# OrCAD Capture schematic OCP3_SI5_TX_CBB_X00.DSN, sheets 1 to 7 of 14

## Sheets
1 PAGE01 - TITLE AND BLOCK DIAG: title: OCP3 SI TX CBB GEN 5; rev: X00; company: Dell, Inc.; note: X07NT; note: 200 Dell Way; note: Round Rock, TX 78682
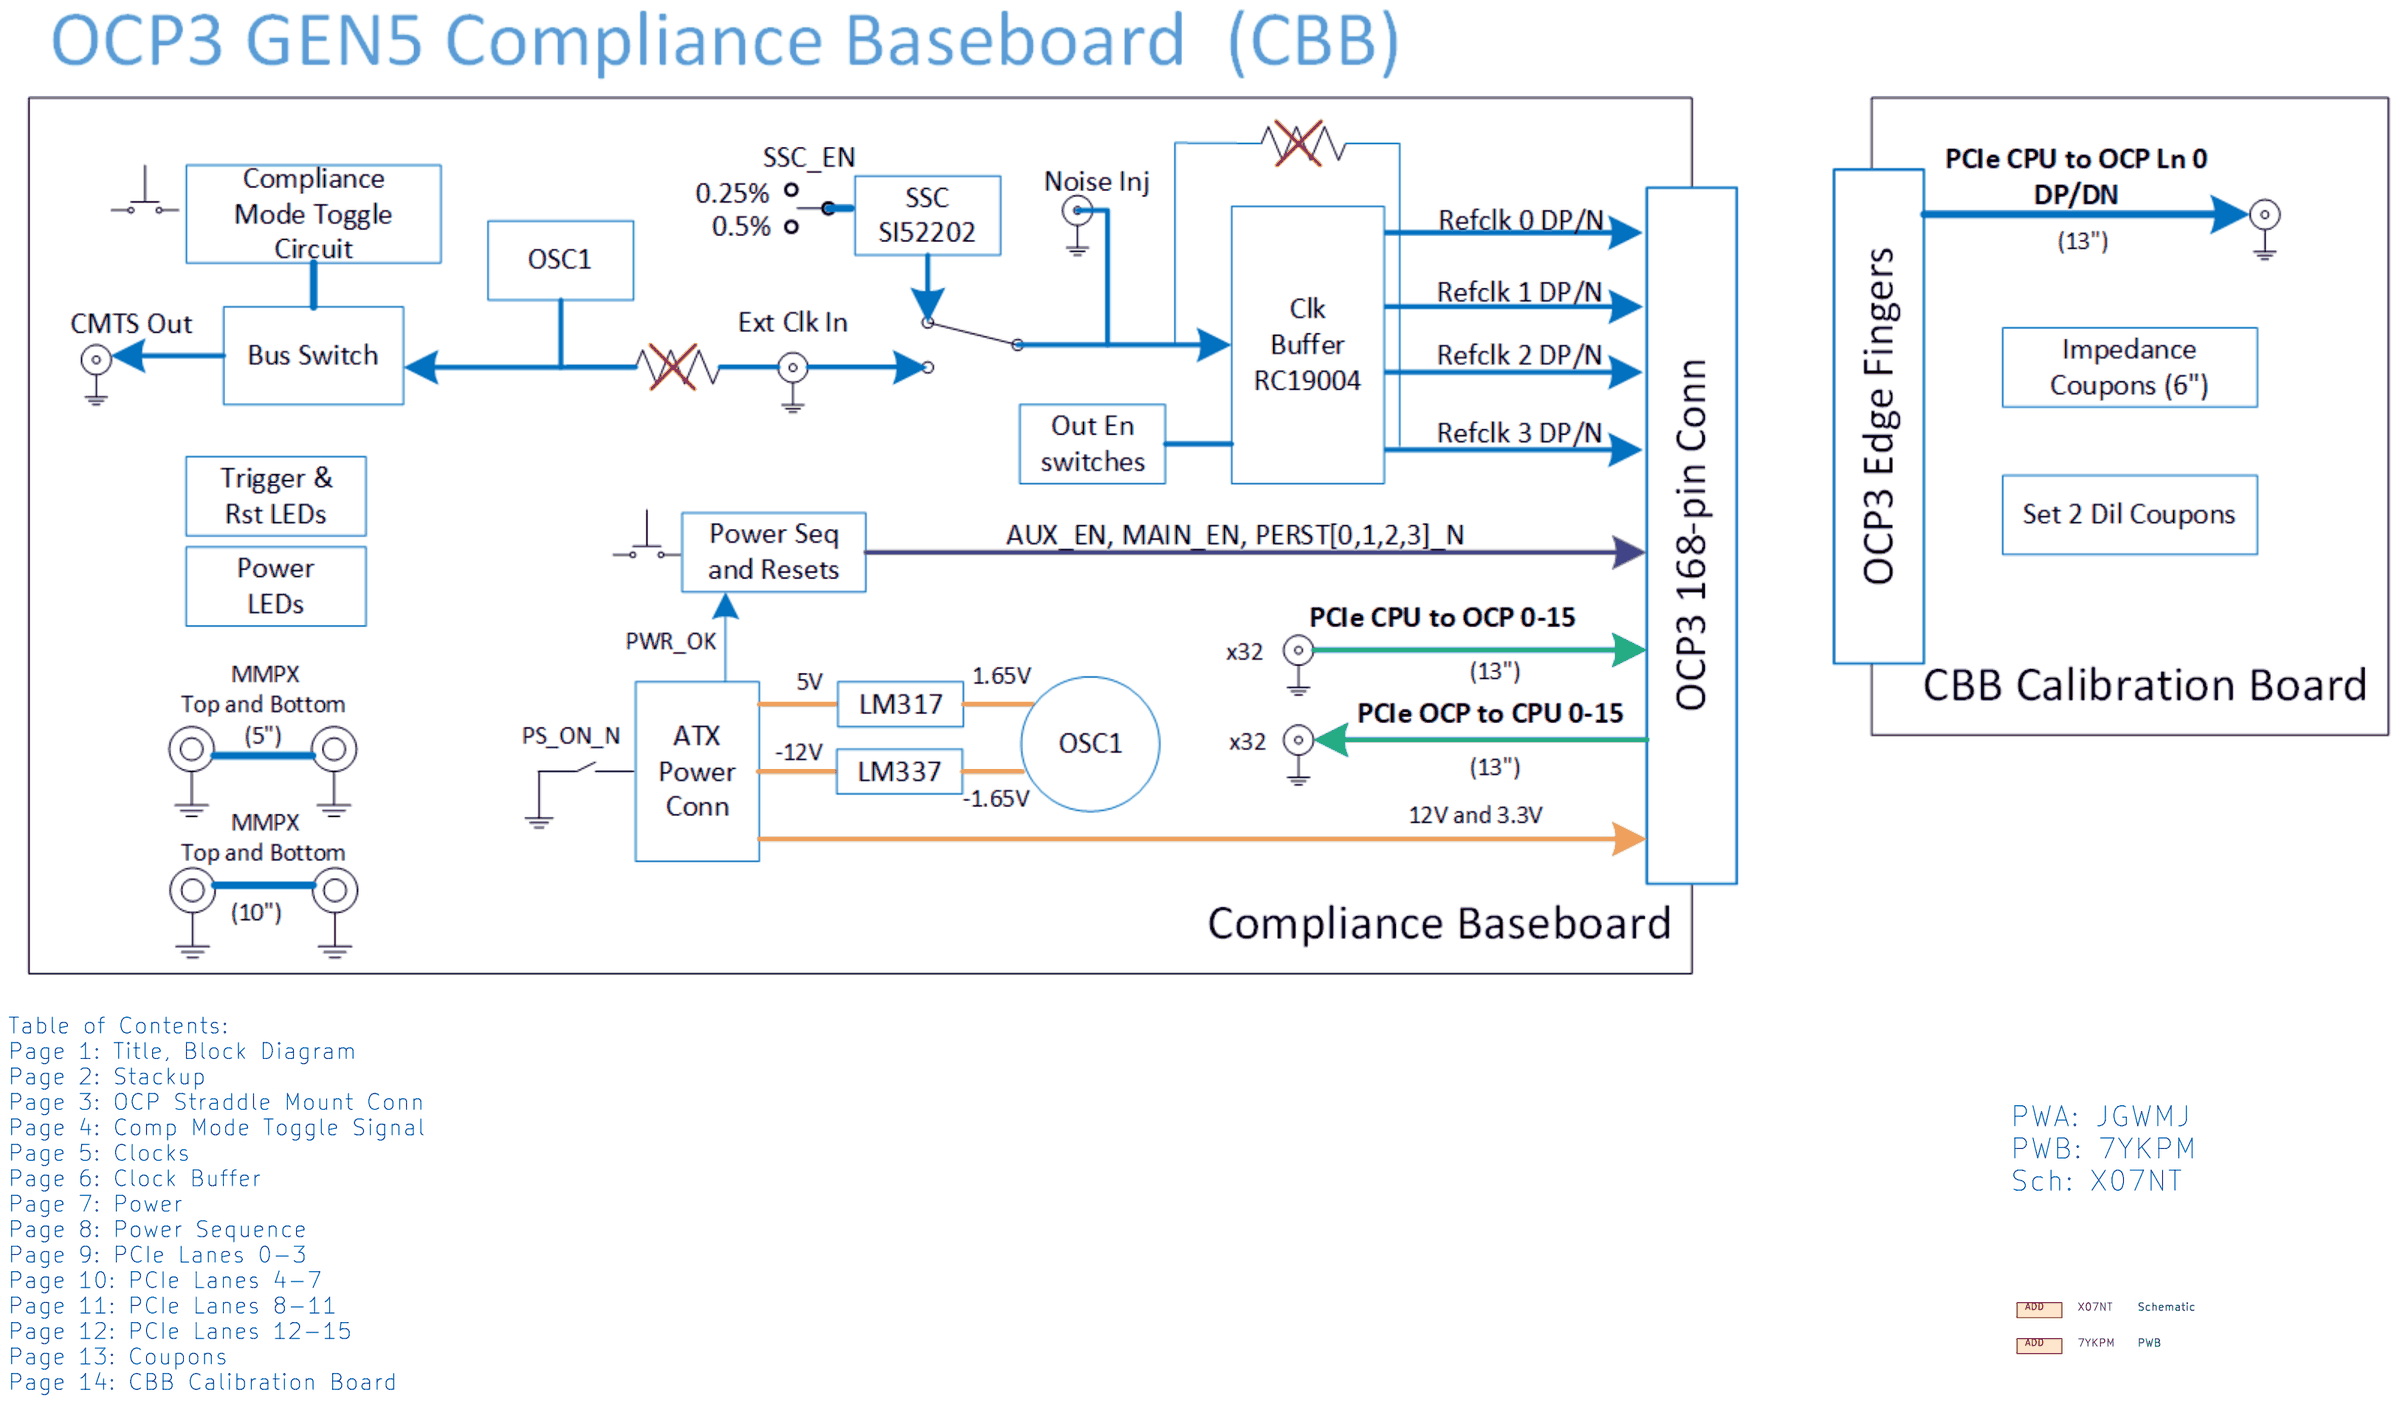
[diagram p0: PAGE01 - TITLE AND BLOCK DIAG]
2 PAGE02 - STACKUP
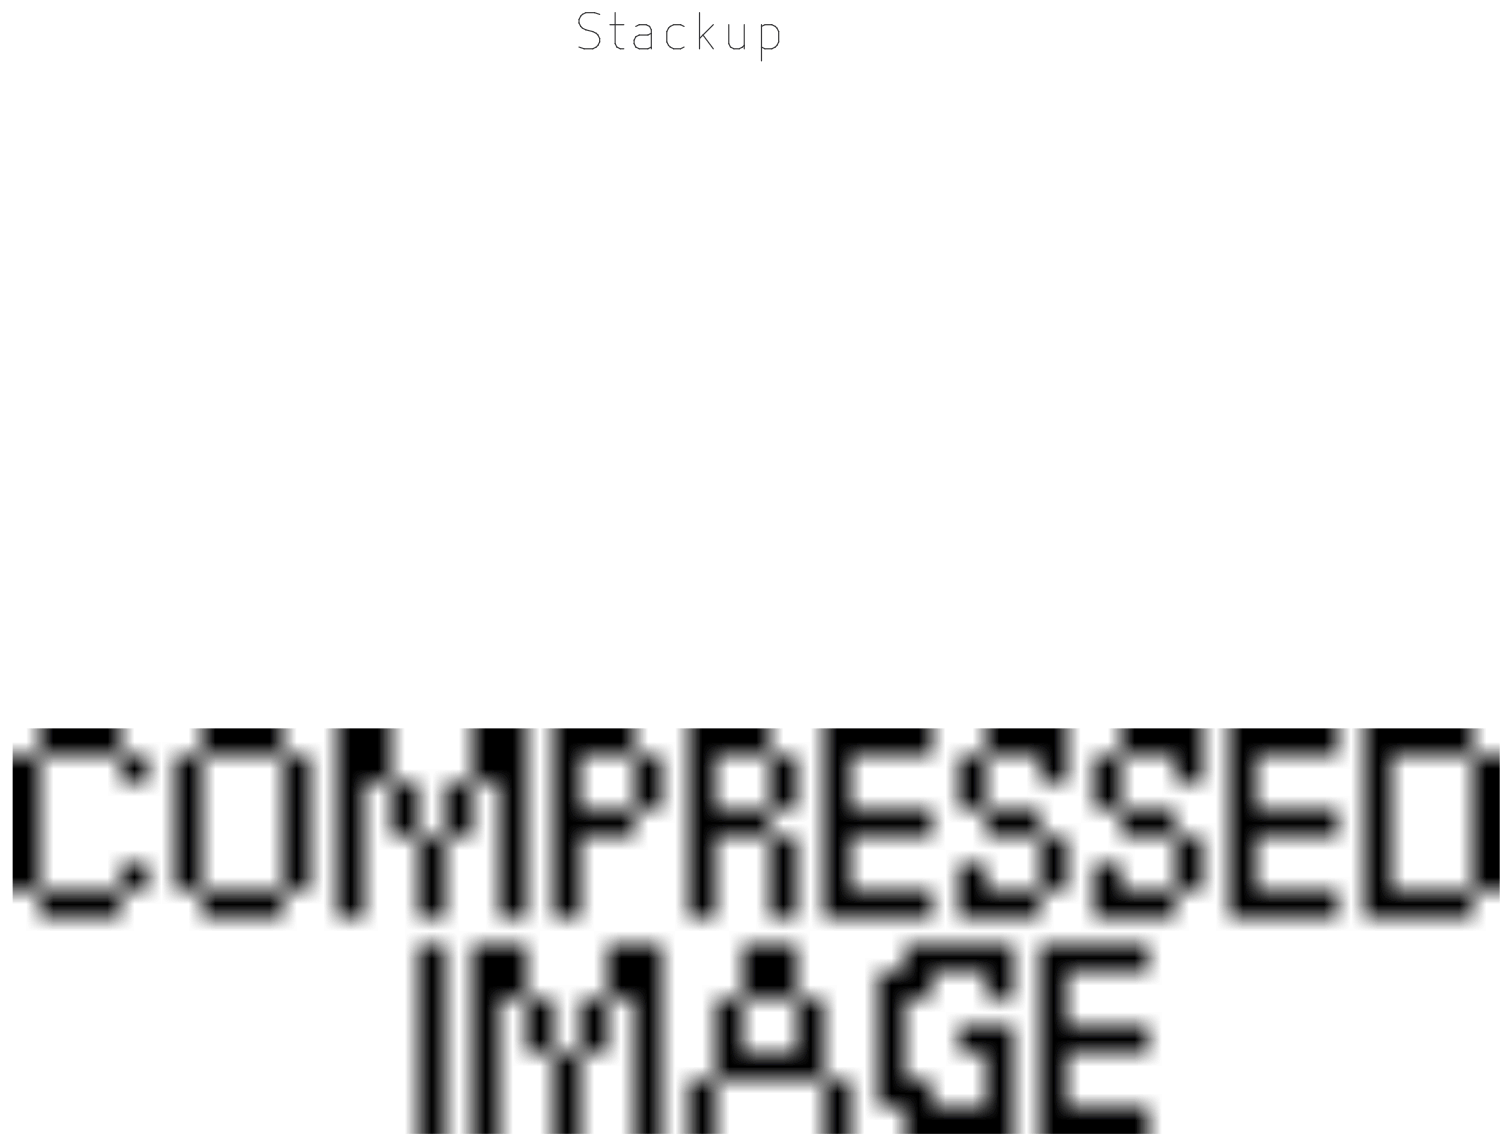
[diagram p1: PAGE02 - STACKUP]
3 PAGE03 - OCP CONNECTOR: size Custom
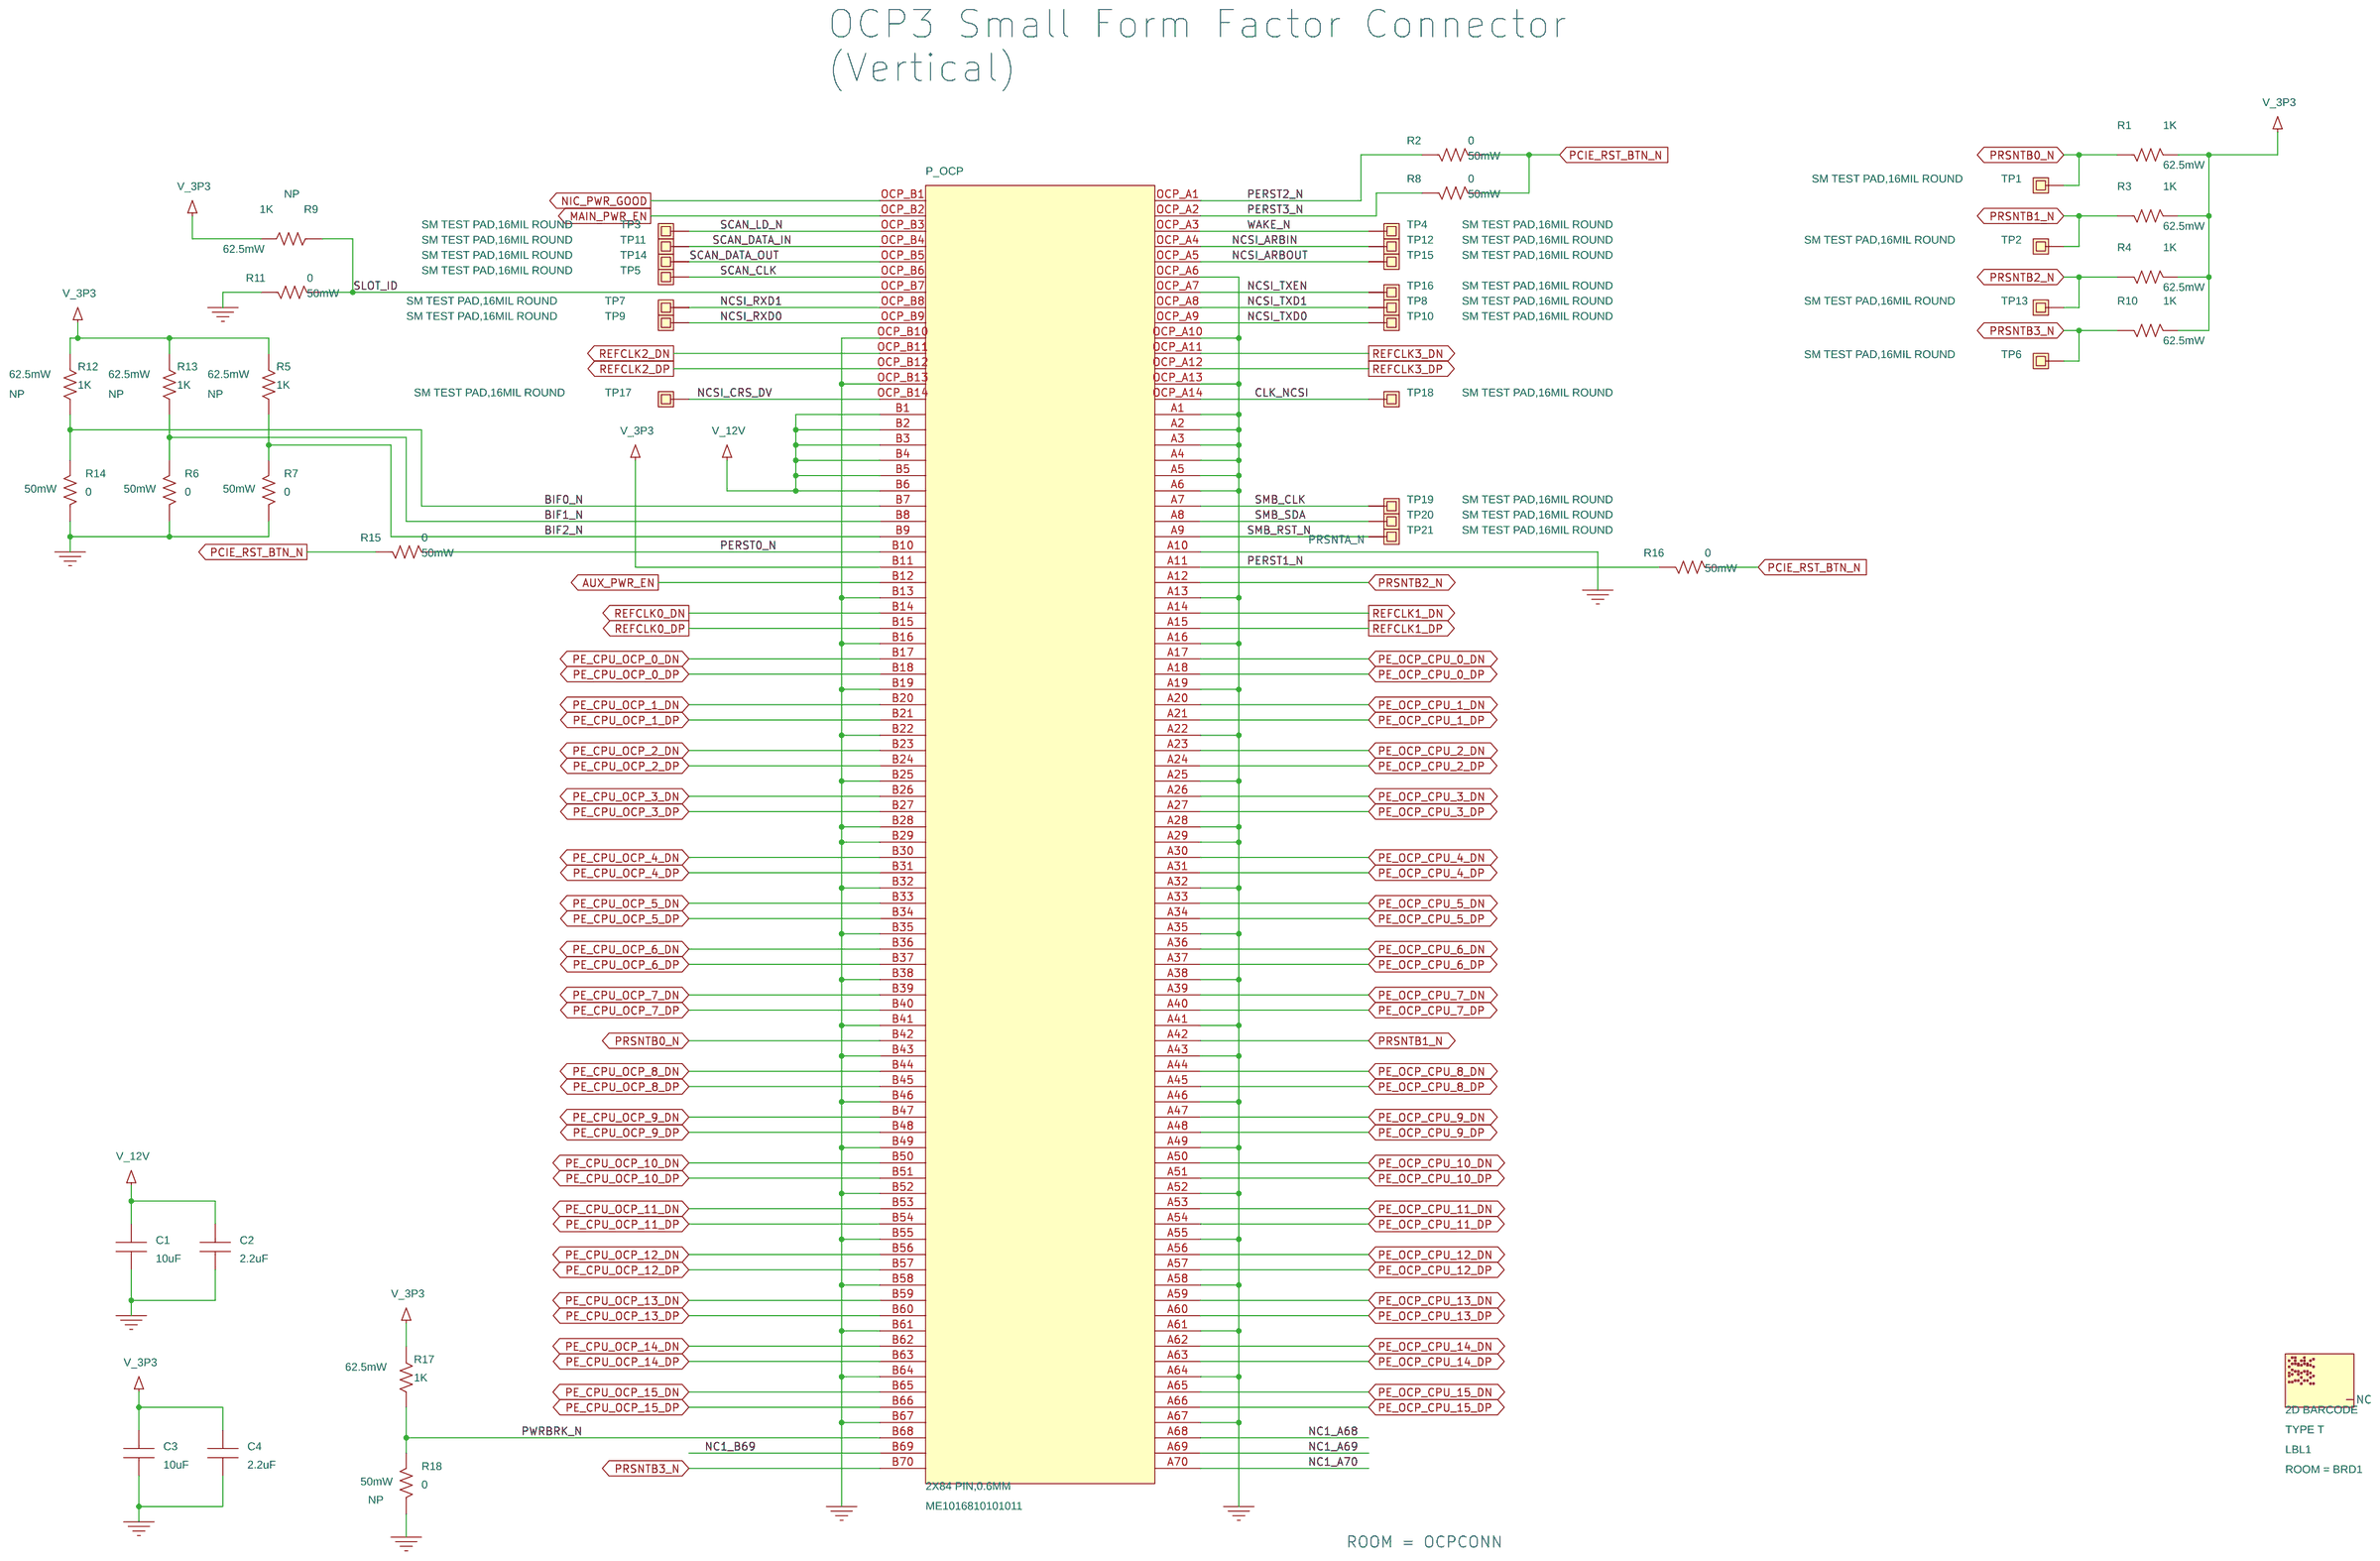
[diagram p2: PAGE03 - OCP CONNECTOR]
4 PAGE04 - COMP MODE TOGGLE: size Custom
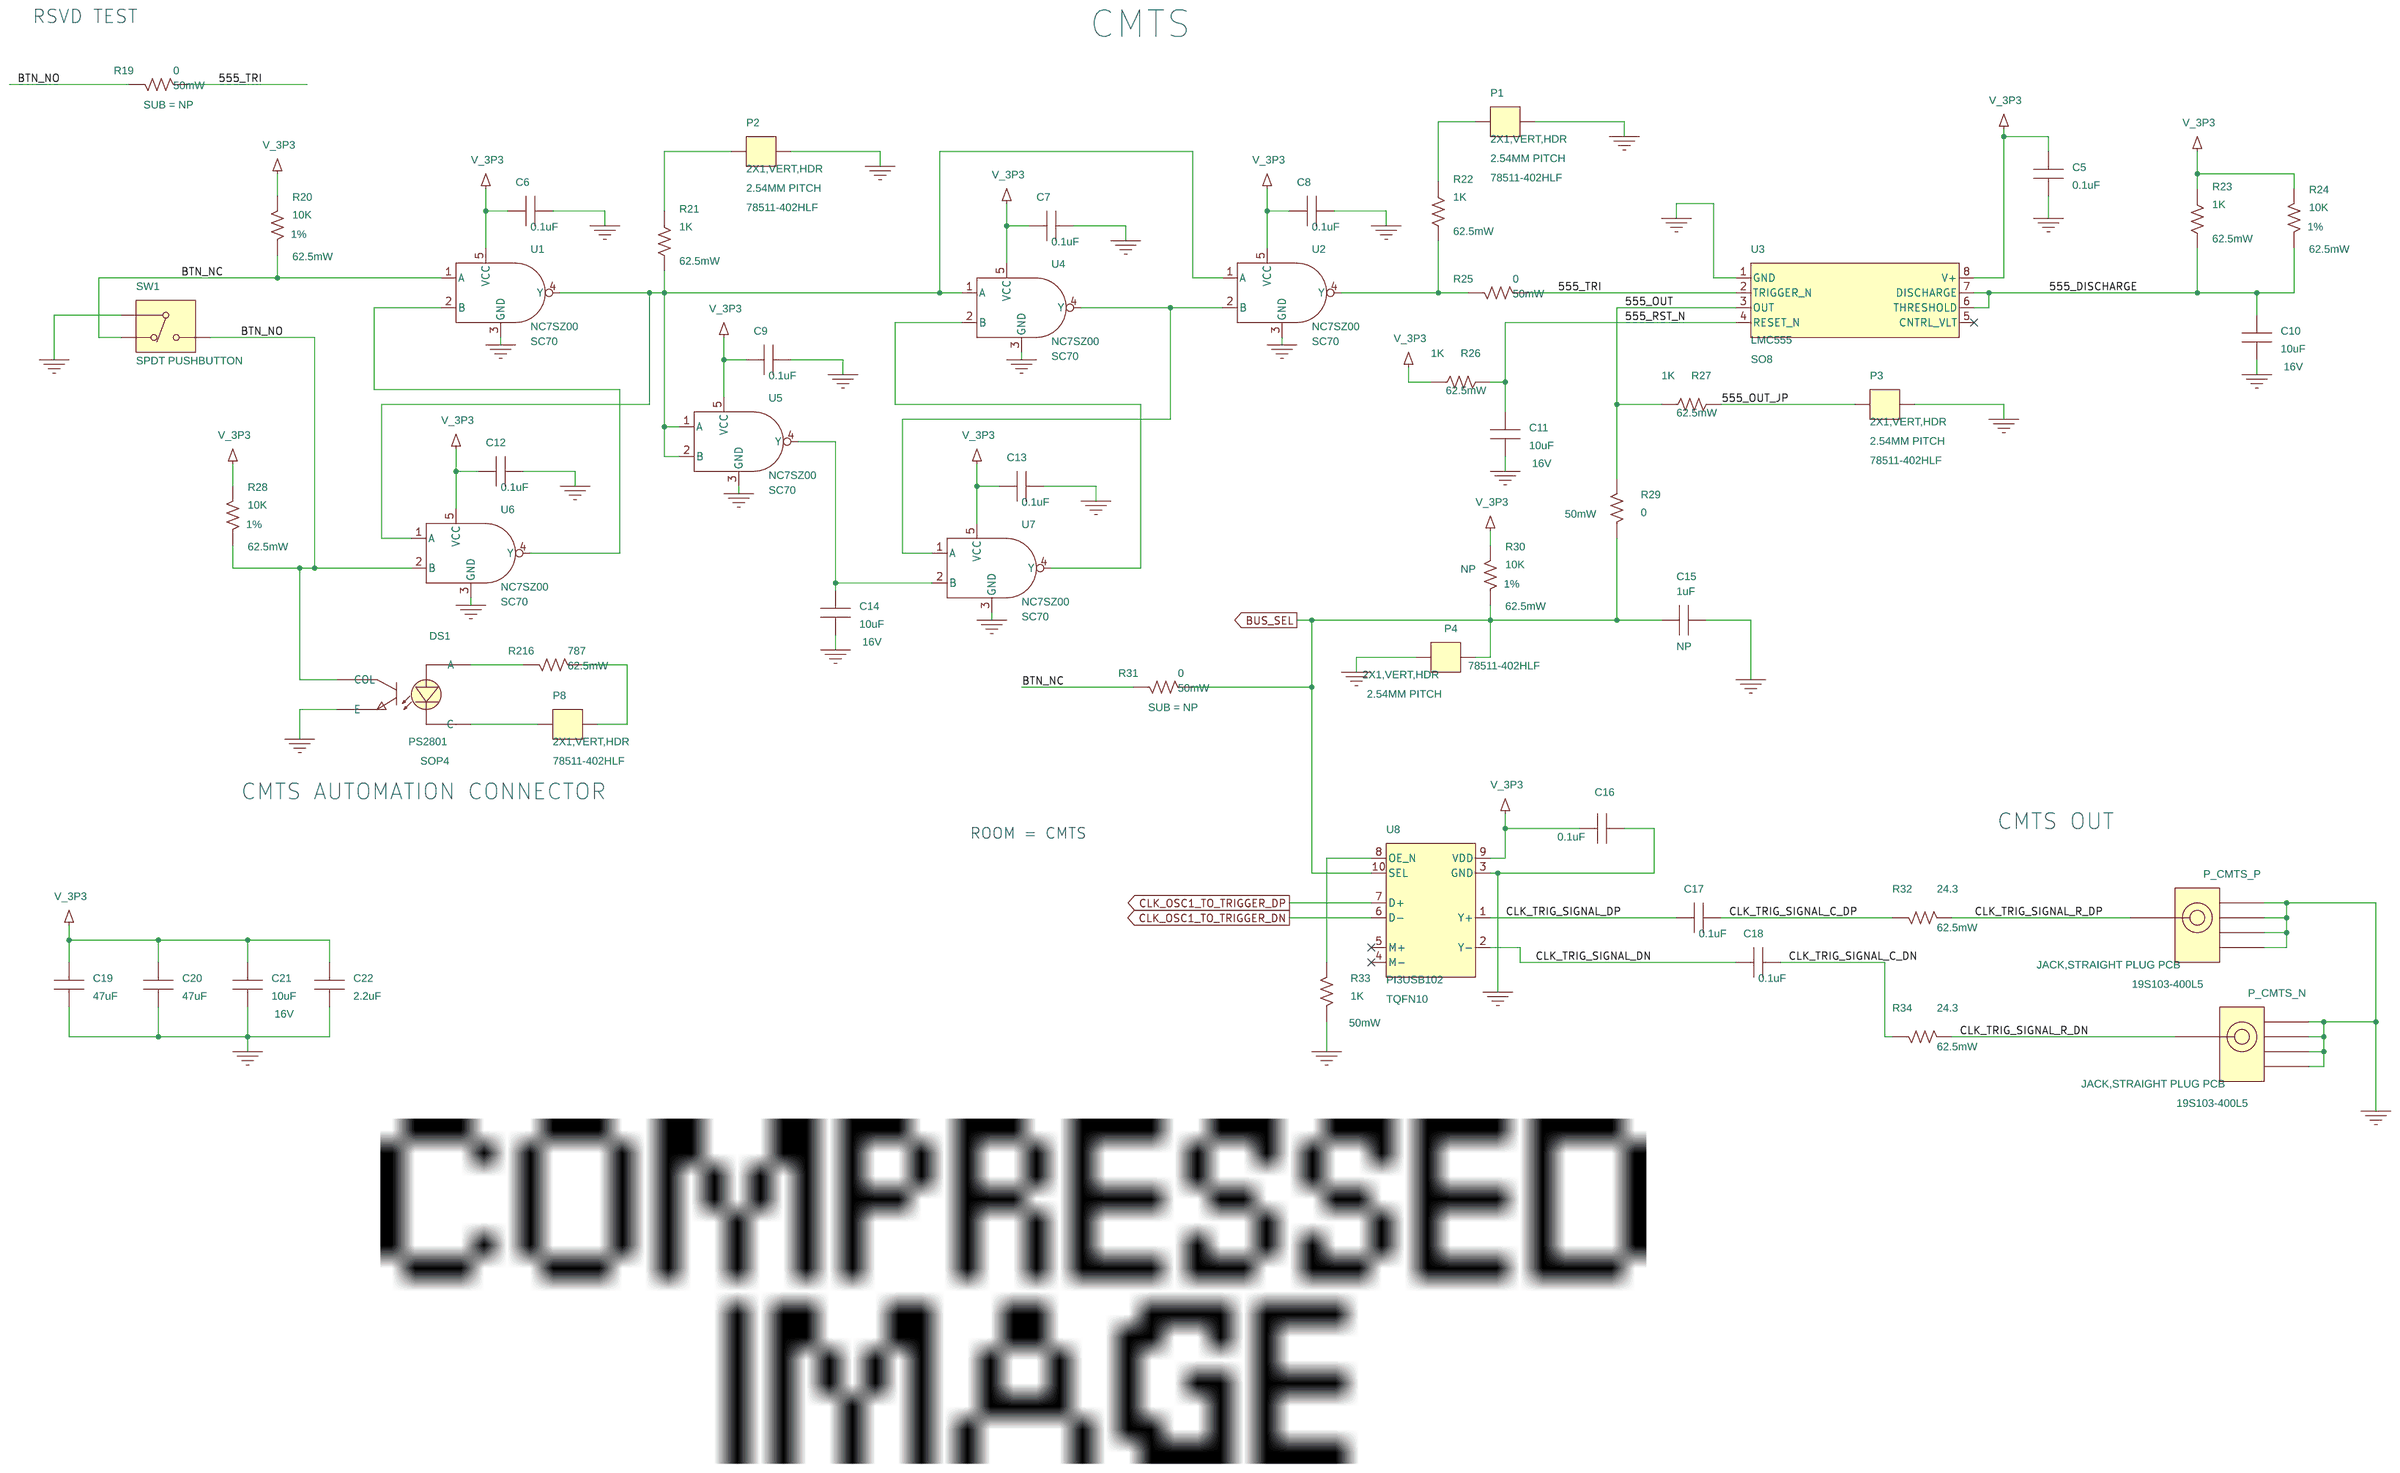
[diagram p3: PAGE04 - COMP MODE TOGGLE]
5 PAGE05 - CLOCKS: size Custom
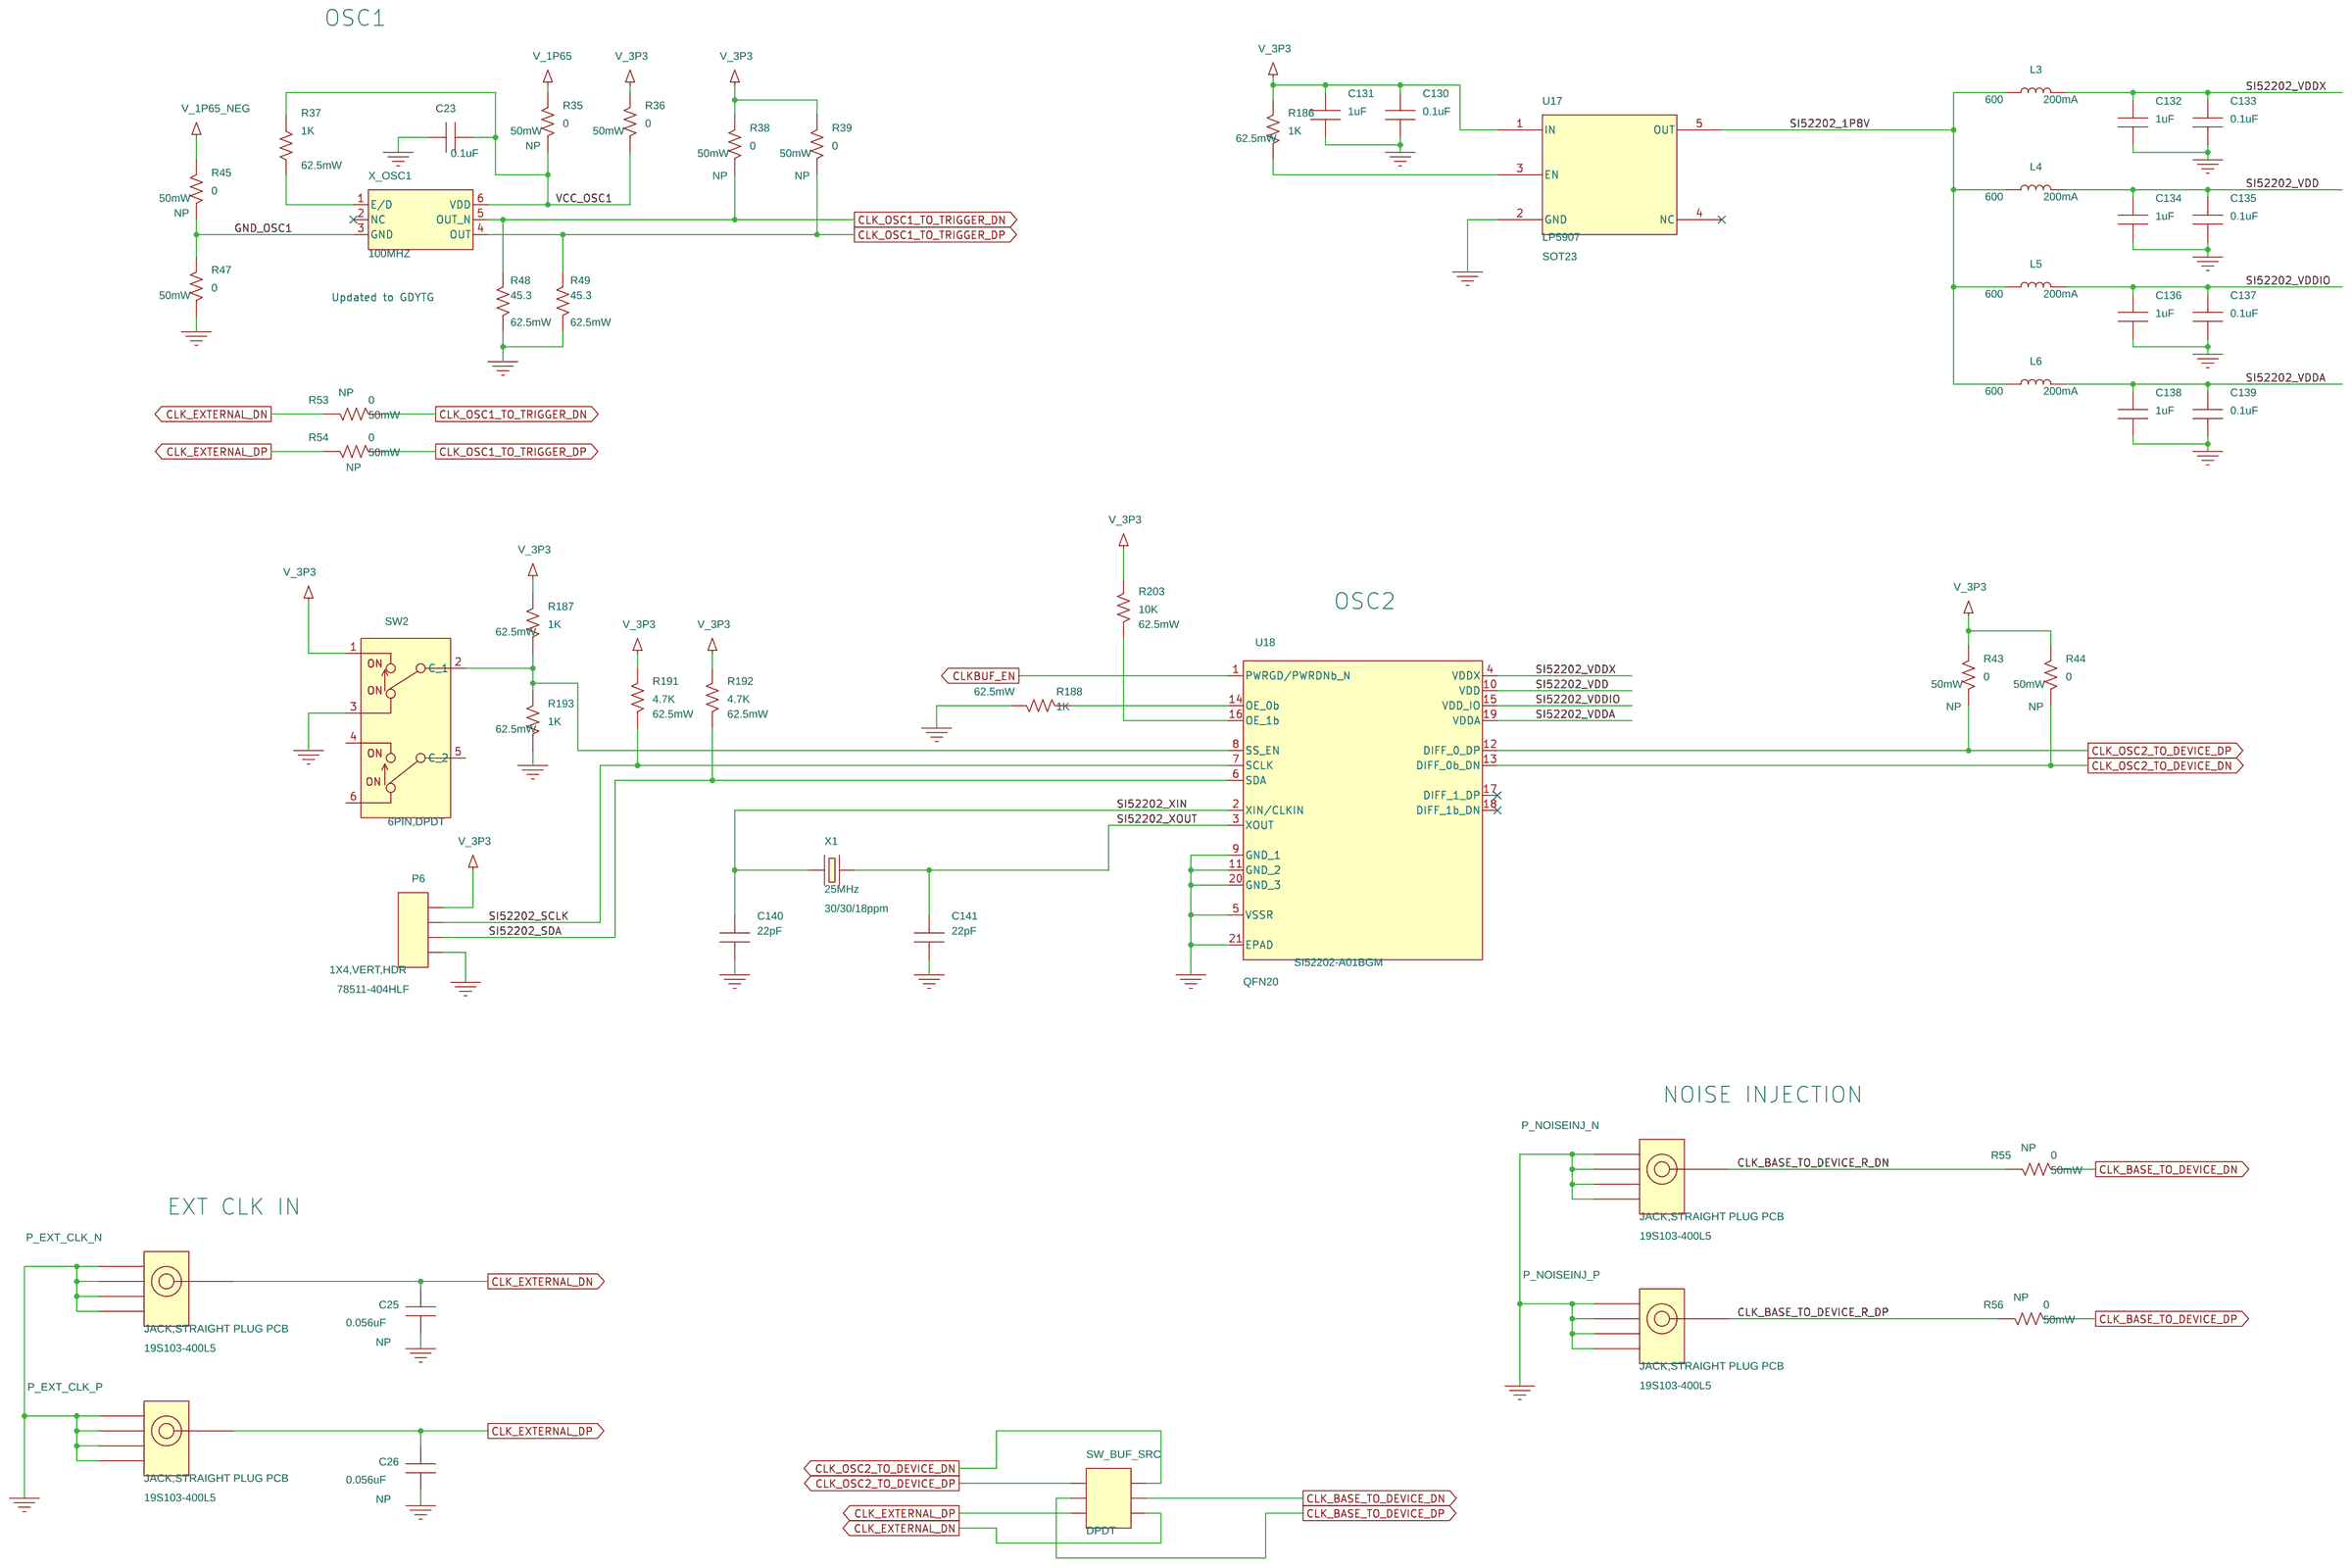
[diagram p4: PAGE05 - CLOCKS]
6 PAGE06 - REFCLK BUFFER: size Custom
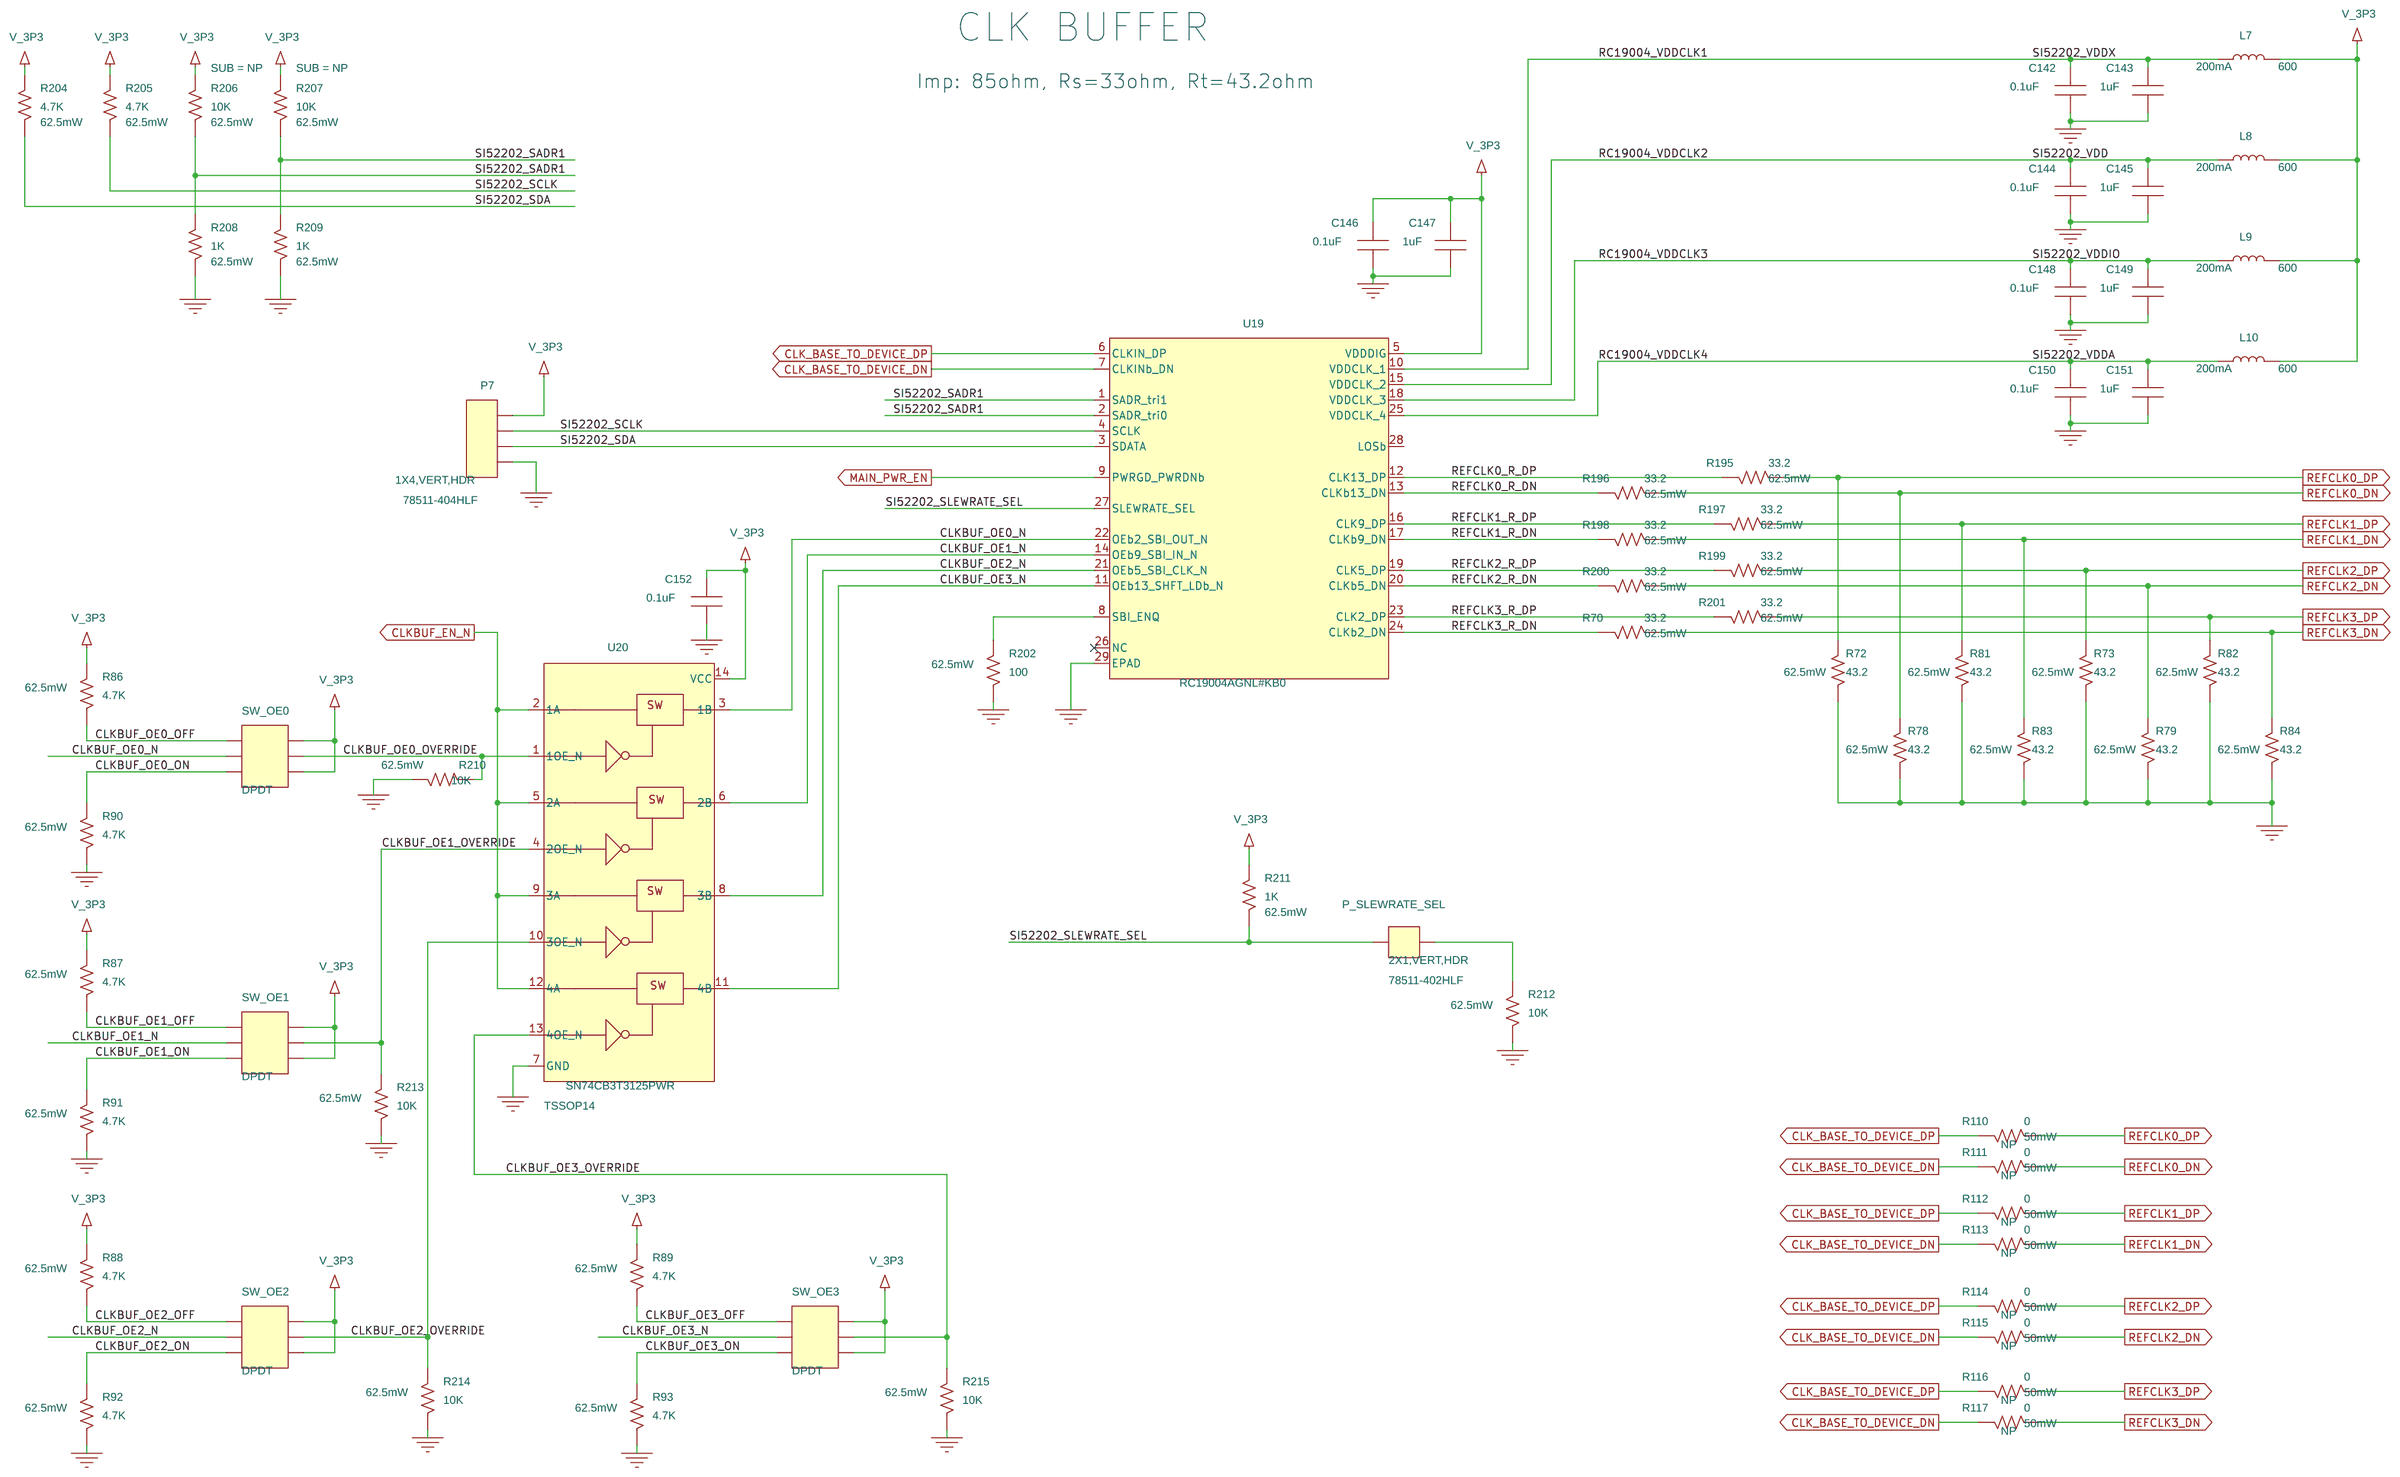
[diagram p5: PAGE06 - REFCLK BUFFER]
7 PAGE07 - POWER: size Custom
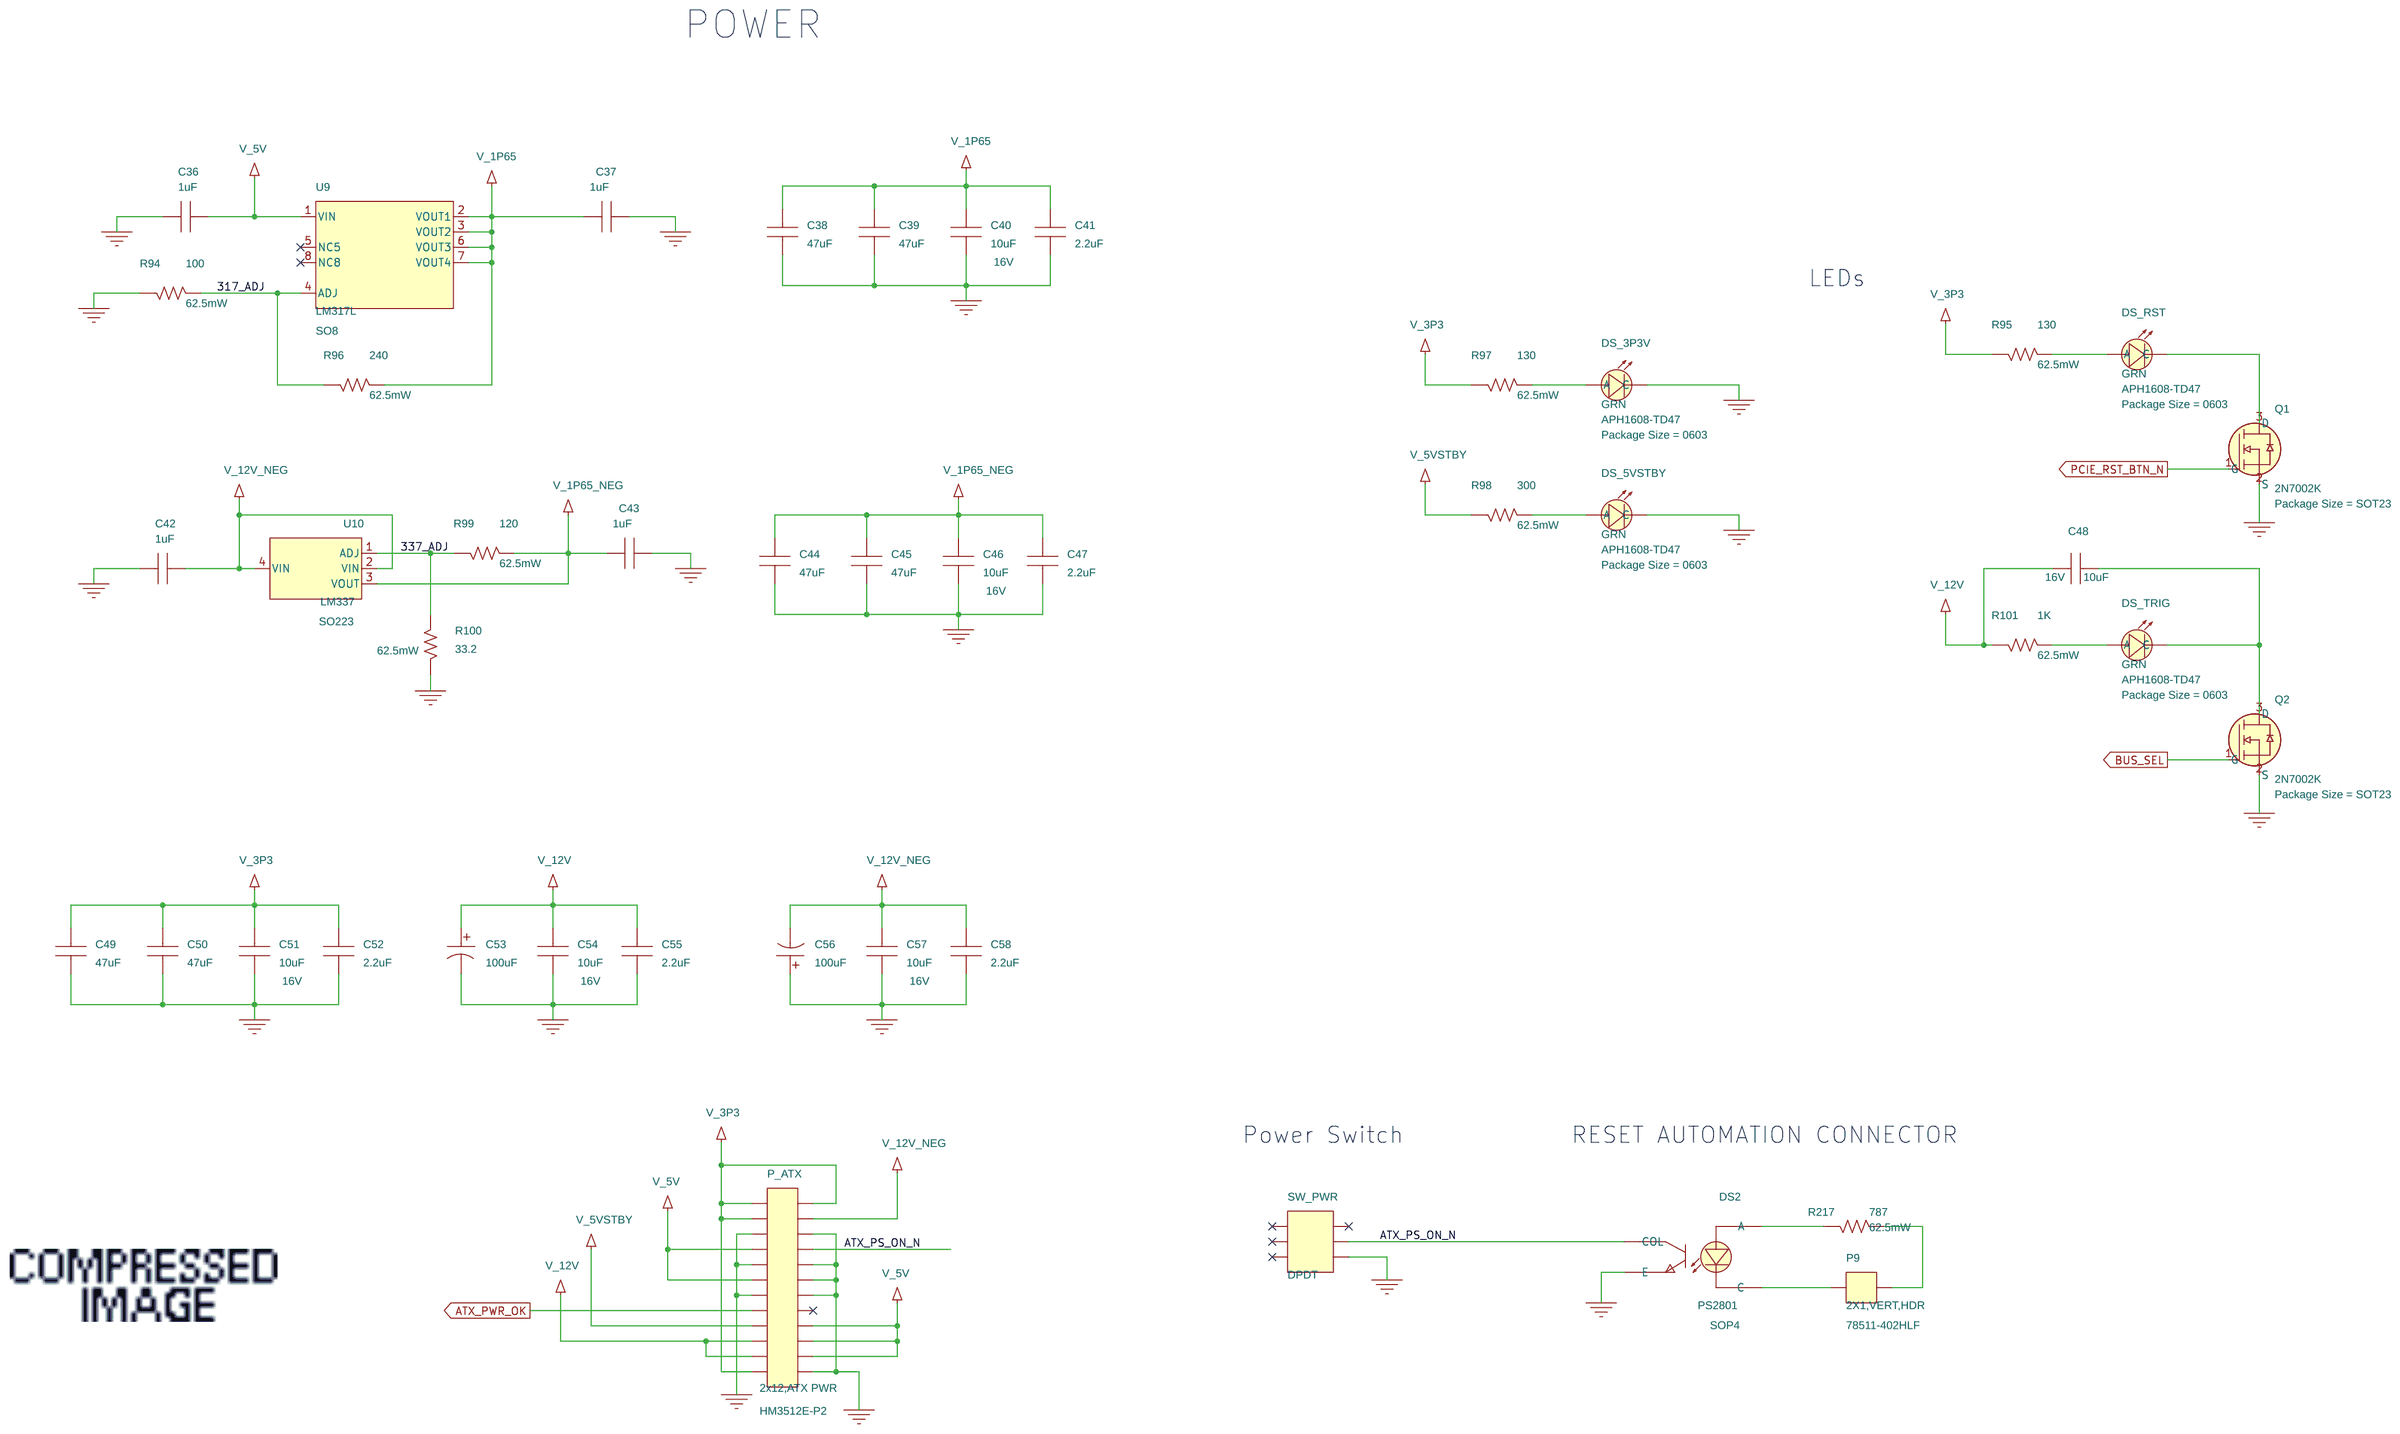
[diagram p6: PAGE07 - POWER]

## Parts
sheet PAGE01 - TITLE AND BLOCK DIAG
PWB  add_part
Schematic  add_part
sheet PAGE03 - OCP CONNECTOR
C1  10uF  [C0603]
C2  2.2uF  [C0603]
C3  10uF  [C0603]
C4  2.2uF  [C0603]
LBL1  2d_label500x437  [2D_LABEL500X437]
P_OCP  2X84 PIN,0.6MM  [C2X84STF_MCE_0P60_5MH_2PG]
R1  1K  [R0402]
R2  0  [R0201]
R3  1K  [R0402]
R4  1K  [R0402]
R5  1K  [R0402]
R6  0  [R0201]
R7  0  [R0201]
R8  0  [R0201]
R9  1K  [R0402]
R10  1K  [R0402]
R11  0  [R0201]
R12  1K  [R0402]
R13  1K  [R0402]
R14  0  [R0201]
R15  0  [R0201]
R16  0  [R0201]
R17  1K  [R0402]
R18  0  [R0201]
TP1  SM TEST PAD,16MIL ROUND  [TP_RD16]
TP2  SM TEST PAD,16MIL ROUND  [TP_RD16]
TP3  SM TEST PAD,16MIL ROUND  [TP_RD16]
TP4  SM TEST PAD,16MIL ROUND  [TP_RD16]
TP5  SM TEST PAD,16MIL ROUND  [TP_RD16]
TP6  SM TEST PAD,16MIL ROUND  [TP_RD16]
TP7  SM TEST PAD,16MIL ROUND  [TP_RD16]
TP8  SM TEST PAD,16MIL ROUND  [TP_RD16]
TP9  SM TEST PAD,16MIL ROUND  [TP_RD16]
TP10  SM TEST PAD,16MIL ROUND  [TP_RD16]
TP11  SM TEST PAD,16MIL ROUND  [TP_RD16]
TP12  SM TEST PAD,16MIL ROUND  [TP_RD16]
TP13  SM TEST PAD,16MIL ROUND  [TP_RD16]
TP14  SM TEST PAD,16MIL ROUND  [TP_RD16]
TP15  SM TEST PAD,16MIL ROUND  [TP_RD16]
TP16  SM TEST PAD,16MIL ROUND  [TP_RD16]
TP17  SM TEST PAD,16MIL ROUND  [TP_RD16]
TP18  SM TEST PAD,16MIL ROUND  [TP_RD16]
TP19  SM TEST PAD,16MIL ROUND  [TP_RD16]
TP20  SM TEST PAD,16MIL ROUND  [TP_RD16]
TP21  SM TEST PAD,16MIL ROUND  [TP_RD16]
sheet PAGE04 - COMP MODE TOGGLE
C5  0.1uF  [C0201]
C6  0.1uF  [C0201]
C7  0.1uF  [C0201]
C8  0.1uF  [C0201]
C9  0.1uF  [C0201]
C10  10uF  [C0603]
C11  10uF  [C0603]
C12  0.1uF  [C0201]
C13  0.1uF  [C0201]
C14  10uF  [C0603]
C15  1uF  [C0603]
C16  0.1uF  [C0201]
C17  0.1uF  [C0201]
C18  0.1uF  [C0201]
C19  47uF  [C1206]
C20  47uF  [C1206]
C21  10uF  [C0603]
C22  2.2uF  [C0603]
DS1  PS2801  [SOIC127P700X230_4N]
P1  2X1,VERT,HDR  [BERG1X2]
P2  2X1,VERT,HDR  [BERG1X2]
P3  2X1,VERT,HDR  [BERG1X2]
P4  2X1,VERT,HDR  [BERG1X2]
P8  2X1,VERT,HDR  [BERG1X2]
P_CMTS_N  JACK,STRAIGHT PLUG PCB  [CON_SMP_PLUG_STF]
P_CMTS_P  JACK,STRAIGHT PLUG PCB  [CON_SMP_PLUG_STF]
R19  0  [R0201]
R20  10K  [R0402]
R21  1K  [R0402]
R22  1K  [R0402]
R23  1K  [R0402]
R24  10K  [R0402]
R25  0  [R0201]
R26  1K  [R0402]
R27  1K  [R0402]
R28  10K  [R0402]
R29  0  [R0201]
R30  10K  [R0402]
R31  0  [R0201]
R32  24.3  [R0402]
R33  1K  [R0201]
R34  24.3  [R0402]
R216  787  [R0402]
SW1  SPDT PUSHBUTTON  [SW3PSMRA_2SH]
U1  NC7SZ00  [SOT65P210X110_5N]
U2  NC7SZ00  [SOT65P210X110_5N]
U3  LMC555  [SOIC127P600X175_8N]
U4  NC7SZ00  [SOT65P210X110_5N]
U5  NC7SZ00  [SOT65P210X110_5N]
U6  NC7SZ00  [SOT65P210X110_5N]
U7  NC7SZ00  [SOT65P210X110_5N]
U8  PI3USB102  [QFN40P130X160X80-10N]
sheet PAGE05 - CLOCKS
C23  0.1uF  [C0201]
C25  0.056uF  [C0402]
C26  0.056uF  [C0402]
C130  0.1uF  [C0201]
C131  1uF  [C0603]
C132  1uF  [C0603]
C133  0.1uF  [C0201]
C134  1uF  [C0603]
C135  0.1uF  [C0201]
C136  1uF  [C0603]
C137  0.1uF  [C0201]
C138  1uF  [C0603]
C139  0.1uF  [C0201]
C140  22pF  [C0402]
C141  22pF  [C0402]
L3  600  [FB1005X55N]
L4  600  [FB1005X55N]
L5  600  [FB1005X55N]
L6  600  [FB1005X55N]
P6  1X4,VERT,HDR  [BERG1X4]
P_EXT_CLK_N  JACK,STRAIGHT PLUG PCB  [CON_SMP_PLUG_STF]
P_EXT_CLK_P  JACK,STRAIGHT PLUG PCB  [CON_SMP_PLUG_STF]
P_NOISEINJ_N  JACK,STRAIGHT PLUG PCB  [CON_SMP_PLUG_STF]
P_NOISEINJ_P  JACK,STRAIGHT PLUG PCB  [CON_SMP_PLUG_STF]
R35  0  [R0201]
R36  0  [R0201]
R37  1K  [R0402]
R38  0  [R0201]
R39  0  [R0201]
R43  0  [R0201]
R44  0  [R0201]
R45  0  [R0201]
R47  0  [R0201]
R48  45.3  [R0402]
R49  45.3  [R0402]
R53  0  [R0201]
R54  0  [R0201]
R55  0  [R0201]
R56  0  [R0201]
R186  1K  [R0402]
R187  1K  [R0402]
R188  1K  [R0402]
R191  4.7K  [R0402]
R192  4.7K  [R0402]
R193  1K  [R0402]
R203  10K  [R0402]
SW2  6PIN,DPDT  [SW_TMD1T5B2M2RE]
SW_BUF_SRC  DPDT  [SW6ST_2P00TH_2MH]
U17  LP5907  [SOT95P280X145_5N]
U18  SI52202-A01BGM  [QFN40P300X300X90-21]
X1  25MHz  [XTAL320X500X110_4N]
X_OSC1  100MHZ  [OSC254P500X700X165_6N]
sheet PAGE06 - REFCLK BUFFER
C142  0.1uF  [C0201]
C143  1uF  [C0603]
C144  0.1uF  [C0201]
C145  1uF  [C0603]
C146  0.1uF  [C0201]
C147  1uF  [C0603]
C148  0.1uF  [C0201]
C149  1uF  [C0603]
C150  0.1uF  [C0201]
C151  1uF  [C0603]
C152  0.1uF  [C0201]
L7  600  [FB1005X55N]
L8  600  [FB1005X55N]
L9  600  [FB1005X55N]
L10  600  [FB1005X55N]
P7  1X4,VERT,HDR  [BERG1X4]
P_SLEWRATE_SEL  2X1,VERT,HDR  [BERG1X2]
R70  33.2  [R0402]
R72  43.2  [R0402]
R73  43.2  [R0402]
R78  43.2  [R0402]
R79  43.2  [R0402]
R81  43.2  [R0402]
R82  43.2  [R0402]
R83  43.2  [R0402]
R84  43.2  [R0402]
R86  4.7K  [R0402]
R87  4.7K  [R0402]
R88  4.7K  [R0402]
R89  4.7K  [R0402]
R90  4.7K  [R0402]
R91  4.7K  [R0402]
R92  4.7K  [R0402]
R93  4.7K  [R0402]
R110  0  [R0201]
R111  0  [R0201]
R112  0  [R0201]
R113  0  [R0201]
R114  0  [R0201]
R115  0  [R0201]
R116  0  [R0201]
R117  0  [R0201]
R195  33.2  [R0402]
R196  33.2  [R0402]
R197  33.2  [R0402]
R198  33.2  [R0402]
R199  33.2  [R0402]
R200  33.2  [R0402]
R201  33.2  [R0402]
R202  100  [R0402]
R204  4.7K  [R0402]
R205  4.7K  [R0402]
R206  10K  [R0402]
R207  10K  [R0402]
R208  1K  [R0402]
R209  1K  [R0402]
R210  10K  [R0402]
R211  1K  [R0402]
R212  10K  [R0402]
R213  10K  [R0402]
R214  10K  [R0402]
R215  10K  [R0402]
SW_OE0  DPDT  [SW6ST_2P00TH_2MH]
SW_OE1  DPDT  [SW6ST_2P00TH_2MH]
SW_OE2  DPDT  [SW6ST_2P00TH_2MH]
SW_OE3  DPDT  [SW6ST_2P00TH_2MH]
U19  RC19004AGNL#KB0  [QFN40P400X400X100-29N]
U20  SN74CB3T3125PWR  [SOP65P640X120-14]
sheet PAGE07 - POWER
C36  1uF  [C0603]
C37  1uF  [C0603]
C38  47uF  [C1206]
C39  47uF  [C1206]
C40  10uF  [C0603]
C41  2.2uF  [C0603]
C42  1uF  [C0603]
C43  1uF  [C0603]
C44  47uF  [C1206]
C45  47uF  [C1206]
C46  10uF  [C0603]
C47  2.2uF  [C0603]
C48  10uF  [C0603]
C49  47uF  [C1206]
C50  47uF  [C1206]
C51  10uF  [C0603]
C52  2.2uF  [C0603]
C53  100uF  [2RAD268D236H098P]
C54  10uF  [C0603]
C55  2.2uF  [C0603]
C56  100uF  [2RAD268D236H098P]
C57  10uF  [C0603]
C58  2.2uF  [C0603]
DS2  PS2801  [SOIC127P700X230_4N]
DS_3P3V  APH1608-TD47  [LEDC1608X65N]
DS_5VSTBY  APH1608-TD47  [LEDC1608X65N]
DS_RST  APH1608-TD47  [LEDC1608X65N]
DS_TRIG  APH1608-TD47  [LEDC1608X65N]
P9  2X1,VERT,HDR  [BERG1X2]
P_ATX  2x12,ATX PWR  [CON_HDR_2X12_ST_TH_PWR]
Q1  2N7002K  [SOT95P237X117_3N]
Q2  2N7002K  [SOT95P237X117_3N]
R94  100  [R0402]
R95  130  [R0402]
R96  240  [R0402]
R97  130  [R0402]
R98  300  [R0402]
R99  120  [R0402]
R100  33.2  [R0402]
R101  1K  [R0402]
R217  787  [R0402]
SW_PWR  DPDT  [SW6ST_2P00TH_2MH]
U9  LM317L  [SOIC127P600X175_8N]
U10  LM337  [SOT230P700X180_4N]

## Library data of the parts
PWB = add_part: Part Number: 7YKPM
Schematic = add_part: Part Number: X07NT
C1 C3 = cap: CAP,10UF,20%,16V,X6S,0603; CLASS: DISCRETE; DPN: 3MRV8; Dielectric Type: X6S; Lead Free: Yes; Lifecycle Phase: A Revision; Manufacturer: MURATA ERIE; Manufacturer PN: GRM188C81C106MA73D; Package Height: 40 MIL; Package Size: 0603; Package Type: SMD; Part Number: 3MRV8; Rev: A00-00; Tolerance: 20%; Voltage: 16V
C2 C4 C22 C41 C47 C52 C55 C58 = cap: CAP,2.2UF,10%,16V,X5R,0603; CLASS: DISCRETE; DPN: J6201; Dielectric Type: X5R; Lead Free: Yes; Lifecycle Phase: A Revision; Manufacturer: MURATA ERIE; Manufacturer PN: GRM188R61C225KE15D; Package Height: 40 MIL; Package Size: 0603; Package Type: SMD; Part Number: J6201; ROOM: BRD1; Rev: A00-00; Tolerance: 10%; Voltage: 16V
LBL1 = 2d_label500x437: LABEL,2D BARCODE,.500X.437,TYPE T; DEVICE: 090730100102; Part Number: HP126; ROOM: BRD1; TAG1: 2D BARCODE; TAG2: TYPE T
P_OCP = c84edg_amp: CON,EC,168P,0.6MM,V,G,SM,OCP; CLASS: IO; DPN: P36NN; Lead Free: Yes; Lifecycle Phase: X Revision; Manufacturer: AMPHENOL; Manufacturer PN: ME1016810101011; Package Height: 9.25 MM; Package Type: SMD; Part Number: P36NN; Rev: X00-00
R1 R3 R4 R10 R17 R21-R23 R26 R27 R37 R101 = res: RES,1K,1/16W,5%,THKFLM,0402; CLASS: DISCRETE; DPN: J5741; Lead Free: Yes; Lifecycle Phase: A Revision; Manufacturer: KOA; Manufacturer PN: RK73B1ETTP102J; Material: Thick Film; Package Height: 16 MIL; Package Size: 0402; Package Type: SMD; Part Number: J5741; Rated Power: 62.5mW; Rev: A00-00; Tolerance: 5%
R2 R6-R8 R11 R14-R16 = res: RES,0,1/20W,5%,THKFLM,0201; ALT_SYMBOLS: (R0201_R4,R0201M_FOX); CLASS: DISCRETE; DPN: YY941; Lead Free: Yes; Lifecycle Phase: A Revision; Manufacturer: KOA; Manufacturer PN: RK73Z1HTQTC; Material: Thick Film; Package Height: 0.33 MM; Package Size: 0201; Package Type: SMD; Part Number: YY941; ROOM: OCPCONN; Rated Power: 50mW; Rev: A00-00; Tolerance: 5%
R5 R9 R12 R13 = res: RES,1K,1/16W,5%,THKFLM,0402; CLASS: DISCRETE; DPN: J5741; Lead Free: Yes; Lifecycle Phase: A Revision; Manufacturer: KOA; Manufacturer PN: RK73B1ETTP102J; Material: Thick Film; Package Height: 16 MIL; Package Size: 0402; Package Type: SMD; Part Number: J5741; Rated Power: 62.5mW; Rev: A00-00; SUB: NP; Tolerance: 5%
R18 R110-R117 = res: RES,0,1/20W,5%,THKFLM,0201; ALT_SYMBOLS: (R0201_R4,R0201M_FOX); CLASS: DISCRETE; DPN: YY941; Lead Free: Yes; Lifecycle Phase: A Revision; Manufacturer: KOA; Manufacturer PN: RK73Z1HTQTC; Material: Thick Film; Package Height: 0.33 MM; Package Size: 0201; Package Type: SMD; Part Number: YY941; ROOM: OCPCONN; Rated Power: 50mW; Rev: A00-00; SUB: NP; Tolerance: 5%
TP1-TP21 = g_tp: TEST POINT 16MIL ROUND; BOM_IGNORE: TRUE; CLASS: DISCRETE; DPN: 00000; Lead Free: N/A; Lifecycle Phase: N/A; Package Height: 1 MIL; Package Type: SMD; Part Number: 160824155312; ROOM: BRD1; Rev: N/A
C5-C9 C12 C13 C16-C18 C23 C130 C133 C135 C137 C139 C142 C144 C146 C148 C150 C152 = cap: CAP,0.1UF,10%,10V,X5R,0201; ALT_SYMBOLS: (CAPC0603X33N,C0201M_FOX,C0201_R4); CLASS: DISCRETE; DPN: MNN3J; Dielectric Type: X5R; Lead Free: Yes; Lifecycle Phase: A Revision; Manufacturer: DARFON ELECTRONICS CORP; Manufacturer PN: C0603X5R104KDT; Package Height: 0.33 MM; Package Size: 0201; Package Type: SMD; Part Number: MNN3J; ROOM: BRD1; Rev: A00-00; Tolerance: 10%; Voltage: 10V
C10 C11 C14 C21 C40 C46 C48 C51 C54 C57 = cap: CAP,10UF,20%,16V,X6S,0603; CLASS: DISCRETE; DEVICE: 090729120217; DPN: 3MRV8; Dielectric Type: X6S; Lead Free: Yes; Lifecycle Phase: A Revision; Manufacturer: MURATA ERIE; Manufacturer PN: GRM188C81C106MA73D; Package Height: 40 MIL; Package Size: 0603; Package Type: SMD; Part Number: 3MRV8; ROOM: BRD1; Rev: A00-00; TOLERANCE: 20%; VOLTAGE: 16V
C15 = cap: CAP,1UF,10%,16V,X7R,0603; CLASS: DISCRETE; DPN: RY497; Dielectric Type: X7R; Lead Free: Yes; Lifecycle Phase: A Revision; Manufacturer: KEMET ELECTRONICS; Manufacturer PN: C0603C105K4RAC; Package Height: 40 MIL; Package Size: 0603; Package Type: SMD; Part Number: RY497; Rev: A00-00; SUB: NP; Tolerance: 10%; Voltage: 16V
C19 C20 C38 C39 C44 C45 C49 C50 = cap: CAP,47UF,20%,10V,X5R,1206; CLASS: DISCRETE; DPN: C2Y5M; Dielectric Type: X5R; Lead Free: Yes; Lifecycle Phase: A Revision; Manufacturer: KEMET ELECTRONICS; Manufacturer PN: C1206C476M8PAC; Package Height: 71 MIL; Package Size: 1206; Package Type: SMD; Part Number: C2Y5M; Rev: A00-00; Tolerance: 20%; Voltage: 10V
DS1 DS2 = ps2801: IC,PS2801,SOP4,OPTOCOUPLER; CLASS: IC; Manufacturer: CALIFORNIA EASTERN LABORATORIE; Manufacturer PN: PS2801-1; Package Height: 2.3 MM; Package Size: SOP4; Package Type: SMD; Part Number: 3TTYD
P1-P4 = g_2x1: CON,HDR,1X2,M,.1X.32,S,T,U,TH; CLASS: IO; DPN: RD013; Lead Free: Yes; Lifecycle Phase: A Revision; Manufacturer: FCI; Manufacturer PN: 78511-402HLF; Package Height: 426 MIL; Package Size: HDR1X2; Package Type: TH; Part Number: RD013; Pin Info: 2.54MM PITCH; ROOM: BRD1; Rev: A00-00
P8 P9 P_SLEWRATE_SEL = g_2x1: CON,HDR,1X2,M,.1X.32,S,T,U,TH; CLASS: IO; Manufacturer: FCI; Manufacturer PN: 78511-402HLF; Package Height: 426 MIL; Package Size: HDR1X2; Package Type: TH; Part Number: RD013
P_CMTS_N P_CMTS_P P_EXT_CLK_N P_EXT_CLK_P P_NOISEINJ_N P_NOISEINJ_P = g_jack_5p: CON,HDR,GF,V,TH; CLASS: IO; DPN: WD7FW; Lead Free: Yes; Lifecycle Phase: Preliminary; Manufacturer: ROSENBERGER HOCHFREQUENZTECHNIK; Manufacturer PN: 19S103-400L5; Package Height: 165.35 MIL; Package Type: SMD; Part Number: WD7FW; ROOM: BRD1; Rev: Introductory
R19 R31 R35 R38 R39 R43-R45 R53-R56 = res: RES,0,1/20W,5%,THKFLM,0201; ALT_SYMBOLS: (R0201_R4,R0201M_FOX); CLASS: DISCRETE; DPN: YY941; Lead Free: Yes; Lifecycle Phase: A Revision; Manufacturer: KOA; Manufacturer PN: RK73Z1HTQTC; Material: Thick Film; Package Height: 0.33 MM; Package Size: 0201; Package Type: SMD; Part Number: YY941; ROOM: BRD1; Rated Power: 50mW; Rev: A00-00; SUB: NP; Tolerance: 5%
R20 R24 R28 = res: RES,10K,1/16W,1%,THKFLM,0402; DEVICE: 090729121122; Part Number: N1256; ROOM: BRD1; Rated Power: 62.5mW; TOLERANCE: 1%
R25 R29 R36 R47 = res: RES,0,1/20W,5%,THKFLM,0201; ALT_SYMBOLS: (R0201_R4,R0201M_FOX); CLASS: DISCRETE; DPN: YY941; Lead Free: Yes; Lifecycle Phase: A Revision; Manufacturer: KOA; Manufacturer PN: RK73Z1HTQTC; Material: Thick Film; Package Height: 0.33 MM; Package Size: 0201; Package Type: SMD; Part Number: YY941; ROOM: BRD1; Rated Power: 50mW; Rev: A00-00; Tolerance: 5%
R30 = res: RES,10K,1/16W,1%,THKFLM,0402; DEVICE: 090729121122; Part Number: N1256; ROOM: BRD1; Rated Power: 62.5mW; SUB: NP; TOLERANCE: 1%
R32 R34 = res: RES,24.3,1/16W,1%,THKFLM,0402; CLASS: DISCRETE; DPN: H8992; Lead Free: Yes; Lifecycle Phase: A Revision; Manufacturer: KOA; Manufacturer PN: RK73H1ET-24R3F; Material: Thick Film; Package Height: 16 MIL; Package Size: 0402; Package Type: SMD; Part Number: H8992; ROOM: BRD1; Rated Power: 62.5mW; Rev: A00-00; Tolerance: 1%
R33 = res: RES,1K,1/20W,1%,THKFLM,0201; ALT_SYMBOLS: (R0201_R4,R0201M_FOX); CLASS: DISCRETE; DPN: 3WWMJ; Lead Free: Yes; Lifecycle Phase: A Revision; Manufacturer: KOA; Manufacturer PN: RK73H1HTQTC1001F; Material: Thick Film; Package Height: 0.33 MM; Package Size: 0201; Package Type: SMD; Part Number: 3WWMJ; ROOM: BRD1; Rated Power: 50mW; Rev: A00-00; Tolerance: 1%
R216 R217 = res: RES,787,1/16W,1%,THKFLM,0402; CLASS: DISCRETE; DPN: H8997; Lead Free: Yes; Lifecycle Phase: A Revision; Manufacturer: SEI ELECTRONICS INC; Manufacturer PN: RMCF0402FT787R; Material: Thick Film; Package Height: 16 MIL; Package Size: 0402; Package Type: SMD; Part Number: U024H; Rated Power: 62.5mW; Rev: A00-00; Tolerance: 1%
SW1 = sw3psmra_spdt: SWT,PB,SPDT,ON-MOM,SMT; CLASS: DISCRETE; DPN: GC8VG; Lead Free: Yes; Lifecycle Phase: X Revision; Manufacturer: C&K; Manufacturer PN: EP12SD1SAPE; Package Height: 5.08 MM; Package Type: SMD; Part Number: GC8VG; ROOM: BRD1; Rev: X00-00; Switch Configuration: SPDT; Switch Type: PUSHBUTTON
U1 U2 U4-U7 = g_nand_1slot_a1_b2: IC,NC7SZ00,SC70,2-INPUT-NAND; CLASS: IC; DPN: RPWR7; Lead Free: Yes; Lifecycle Phase: A Revision; Manufacturer: FAIRCHILD; Manufacturer PN: NC7SZ00P5X; Package Height: 1.1 MM; Package Size: SC70; Package Type: SMD; Part Number: RPWR7; ROOM: BRD1; Rev: A00-00
U3 = lmc555: IC,C555,SO8,CMOS TIMER; CLASS: IC; DPN: 83011; Lead Free: No; Lifecycle Phase: A Revision; Manufacturer: NATIONAL SEMICONDUCTOR; Manufacturer PN: LMC555CM; Package Height: 1.75 MM; Package Size: SO8; Package Type: SMD; Part Number: 83011; ROOM: BRD1; Rev: A00-00
U8 = pi3usb102-10: IC,PI3USB102,TQFN10,USB2.0-MUX; CLASS: IC; DPN: GVY50; Lead Free: Yes; Lifecycle Phase: X Revision; Manufacturer: PERICOM SEMICONDUCTOR; Manufacturer PN: PI3USB102ZLEX; Package Height: 0.8 MM; Package Size: TQFN10; Package Type: SMD; Part Number: GVY50; ROOM: BRD1; Rev: X00-00
C25 C26 = cap: CAP,0.056UF,10%,10V,X7R,0402; CLASS: DISCRETE; DPN: KN9YT; Dielectric Type: X7R; Lead Free: Yes; Lifecycle Phase: Preliminary; Manufacturer: SAMSUNG; Manufacturer PN: CL05B563KP5NNNC; Package Height: 24 MIL; Package Size: 0402; Package Type: SMD; Part Number: KN9YT; ROOM: BRD1; Rev: Introductory; SUB: NP; Tolerance: 10%; Voltage: 10V
C131 C132 C134 C136 C138 C143 C145 C147 C149 C151 = cap: CAP,1UF,10%,16V,X7R,0603; CLASS: DISCRETE; DPN: MNN3J; Dielectric Type: X7R; Lead Free: Yes; Lifecycle Phase: A Revision; Manufacturer: KEMET ELECTRONICS; Manufacturer PN: C0603C105K4RAC; Package Height: 40 MIL; Package Size: 0603; Package Type: SMD; Part Number: RY497; ROOM: BRD1; Rev: A00-00; Tolerance: 10%; Voltage: 16V
C140 C141 = cap: CAP,22PF,5%,50V,C0G,0402; CLASS: DISCRETE; DPN: KN9YT; Dielectric Type: C0G; Lead Free: Yes; Lifecycle Phase: Preliminary; Manufacturer: KEMET ELECTRONICS; Manufacturer PN: C0402C220J5GAC; Package Height: 24 MIL; Package Size: 0402; Package Type: SMD; Part Number: M5278; ROOM: BRD1; Rev: Introductory; Tolerance: 5%; Voltage: 50V
L3-L10 = g_ind: FE,BEAD,200MA,0402,600OHM; CLASS: DISCRETE; Manufacturer: MURATA ERIE; Manufacturer PN: BLM15BD601SN1; Package Height: 0.55 MM; Package Size: 0402; Package Type: SMD; Part Number: XJ237; Rated Current: 200mA
P6 P7 = g_1x4: CON,HDR,1X4,M,2.54MM,S,T,U,TH; CLASS: IO; Manufacturer: FCI; Manufacturer PN: 78511-404HLF; Package Height: 426 MIL; Package Size: HDR1X4; Package Type: TH; Part Number: Y9609
R48 R49 = res: RES,45.3,1/16W,1%,THKFLM,0402; CLASS: DISCRETE; DPN: DP596; Lead Free: Yes; Lifecycle Phase: A Revision; Manufacturer: KOA; Manufacturer PN: RK73H1ETTP45R3F; Material: Thick Film; Package Height: 16 MIL; Package Size: 0402; Package Type: SMD; Part Number: DP596; Rated Power: 62.5mW; Rev: A00-00; Tolerance: 1%
R186-R188 R193 R208 R209 R211 = res: RES,1K,1/16W,5%,THKFLM,0402; CLASS: DISCRETE; DPN: YY941; Lead Free: Yes; Lifecycle Phase: A Revision; Manufacturer: KOA; Manufacturer PN: RK73B1ETTP102J; Material: Thick Film; Package Height: 16 MIL; Package Size: 0402; Package Type: SMD; Part Number: J5741; ROOM: BRD1; Rated Power: 62.5mW; Rev: A00-00; Tolerance: 5%
R191 R192 R204 R205 = res: RES,4.7K,1/16W,5%,THKFLM,0402; CLASS: DISCRETE; DPN: YY941; Lead Free: Yes; Lifecycle Phase: A Revision; Manufacturer: KOA; Manufacturer PN: RK73B1ETTP472J; Material: Thick Film; Package Height: 16 MIL; Package Size: 0402; Package Type: SMD; Part Number: N5300; ROOM: BRD1; Rated Power: 62.5mW; Rev: A00-00; Tolerance: 5%
R203 R210 = res: RES,10K,1/16W,1%,THKFLM,0402; CLASS: DISCRETE; DPN: YY941; Lead Free: Yes; Lifecycle Phase: A Revision; Manufacturer: KOA; Manufacturer PN: RK73H1ETTP1002F; Material: Thick Film; Package Height: 16 MIL; Package Size: 0402; Package Type: SMD; Part Number: N1256; ROOM: BRD1; Rated Power: 62.5mW; Rev: A00-00; Tolerance: 1%
SW2 = TMD1T5B2M2RE: SWT,TH,DPDT,VERTICAL,6 PIN; Manufacturer: TE CONNECTIVITY; Package Height: 22.09 MM; Package Type: TH; Part Number: 9X454; Switch Configuration: DPDT
SW_BUF_SRC SW_OE0-SW_OE3 SW_PWR = g_2x3_ss: SWT,SL,DPDT,0.2A@30VDC; CLASS: DISCRETE; DPN: 0C94G; Lead Free: Yes; Lifecycle Phase: X Revision; Manufacturer: E-SWITCH; Manufacturer PN: EG2207; Package Height: 7.9 MM; Package Type: TH; Part Number: 0C94G; ROOM: BRD1; Rev: X00-00
U17 = lp5907: IC,LP5907,SOT23,LINEAR-REG,LDO; CLASS: IC; Manufacturer: TEXAS INSTRUMENTS; Manufacturer PN: LP5907MFX-1.8/NOPB; Package Height: 1.45 MM; Package Size: SOT23; Package Type: SMD; Part Number: TVXF2
U18 = Si52202-A01BGM: IC,CLKGEN,2OUTS,QFN20,PCIE5; Manufacturer: SKYWORKS SOLUTIONS INC; Package Height: 0.9 MM; Package Size: QFN20; Package Type: SMD; Part Number: 2F6G6
X1 = g_xtal_2x1_4p_24nc: XTAL,25.0M,30/30/18,4-PAD; CLASS: DISCRETE; Frequency Tolerance: 30/30/18ppm; Manufacturer: FOX ELECTRONICS; Manufacturer PN: 738B-25-20; Package Height: 1.1 MM; Package Size: 5.0X3.2; Package Type: SMD; Part Number: WW117
X_OSC1 = g_osc_6p: OSC,100M,50,LVPECL,3.3V; CLASS: DISCRETE; DPN: GDYTG; Lead Free: Yes; Lifecycle Phase: X Revision; Manufacturer: EPSON; Manufacturer PN: SG7050 EBN 100.000000MHZ CJGA; Package Height: 1.65 MM; Package Type: SMD; Part Number: GDYTG; Rev: X00-00
R70 R100 R195-R201 = res: RES,33.2,1/16W,1%,THKFLM,0402; CLASS: DISCRETE; DPN: H8997; Lead Free: Yes; Lifecycle Phase: A Revision; Manufacturer: KOA; Manufacturer PN: RK73H1ETTP-33R2F; Material: Thick Film; Package Height: 16 MIL; Package Size: 0402; Package Type: SMD; Part Number: H8997; Rated Power: 62.5mW; Rev: A00-00; Tolerance: 1%
R72 R73 R78 R79 R81-R84 = res: RES,43.2,1/16W,1%,THKFLM,0402; CLASS: DISCRETE; DPN: J8383; Lead Free: Yes; Lifecycle Phase: A Revision; Manufacturer: KOA; Manufacturer PN: RK73H1ET-43R2F; Material: Thick Film; Package Height: 16 MIL; Package Size: 0402; Package Type: SMD; Part Number: J8383; Rated Power: 62.5mW; Rev: A00-00; Tolerance: 1%
R86-R93 = res: RES,4.7K,1/16W,5%,THKFLM,0402; CLASS: DISCRETE; DPN: N5300; Lead Free: Yes; Lifecycle Phase: A Revision; Manufacturer: KOA; Manufacturer PN: RK73B1ETTP472J; Material: Thick Film; Package Height: 16 MIL; Package Size: 0402; Package Type: SMD; Part Number: N5300; Rated Power: 62.5mW; Rev: A00-00; Tolerance: 5%
R202 = res: RES,100,1/16W,5%,THKFLM,0402; CLASS: DISCRETE; DPN: N5300; Lead Free: Yes; Lifecycle Phase: A Revision; Manufacturer: KOA; Manufacturer PN: RK73B1ETTP101J; Material: Thick Film; Package Height: 16 MIL; Package Size: 0402; Package Type: SMD; Part Number: C7553; Rated Power: 62.5mW; Rev: A00-00; Tolerance: 5%
R206 R207 = res: RES,10K,1/16W,1%,THKFLM,0402; CLASS: DISCRETE; DPN: YY941; Lead Free: Yes; Lifecycle Phase: A Revision; Manufacturer: KOA; Manufacturer PN: RK73H1ETTP1002F; Material: Thick Film; Package Height: 16 MIL; Package Size: 0402; Package Type: SMD; Part Number: N1256; ROOM: BRD1; Rated Power: 62.5mW; Rev: A00-00; SUB: NP; Tolerance: 1%
R212-R215 = res: RES,10K,1/16W,1%,THKFLM,0402; CLASS: DISCRETE; DPN: N5300; Lead Free: Yes; Lifecycle Phase: A Revision; Manufacturer: KOA; Manufacturer PN: RK73H1ETTP1002F; Material: Thick Film; Package Height: 16 MIL; Package Size: 0402; Package Type: SMD; Part Number: N1256; Rated Power: 62.5mW; Rev: A00-00; Tolerance: 1%
U19 = RC19004AGNL-KB0_1: IC,CLKBFR,4X4,28VFQFPN; Manufacturer: RENESAS TECHNOLOGY CORPORATION; Package Height: TBD MM; Part Number: XFGFC
U20 = SN74CB3T3125PWR: IC,74CB3T3125,TSSOP14,BUS-SWT; Manufacturer: TEXAS INSTRUMENTS; Package Height: 1.2 MM; Package Size: TSSOP14; Package Type: SMD; Part Number: 8WR5P
C36 C37 C42 C43 = cap: CAP,1UF,10%,50V,X5R,0603; CLASS: DISCRETE; DPN: 15D2J; Dielectric Type: X5R; Lead Free: Yes; Lifecycle Phase: A Revision; Manufacturer: MURATA ERIE; Manufacturer PN: GRM188R61H105KAALD; Package Height: 40 MIL; Package Size: 0603; Package Type: SMD; Part Number: 15D2J; Rev: A00-00; Tolerance: 10%; Voltage: 50V
C53 C56 = cap_p: CAP,100UF,20%,16V,AORG,6.3X6MM; CLASS: DISCRETE; DPN: PTT5Y; Dielectric Type: AORG; Lead Free: Yes; Lifecycle Phase: A Revision; Manufacturer: SANYO ENERGY; Manufacturer PN: 16SEPC100M; Package Height: 236 MIL; Package Size: 6.3X6; Package Type: TH; Part Number: PTT5Y; Rev: A00-00; Tolerance: 20%; Voltage: 16V
DS_3P3V DS_5VSTBY DS_RST DS_TRIG = g_led_a1_c2: LED,0603,CLR,GRN,2V,20MA,35MCD; CLASS: DISCRETE; DPN: UJ387; LED Color: GRN; Lead Free: Yes; Lifecycle Phase: A Revision; Manufacturer: KINGBRIGHT CORPORATION; Package Height: 0.65 MM; Package Size: 0603; Package Type: SMD; Part Number: UJ387; ROOM: BRD1; Rev: A01-00; Voltage: 2V
P_ATX = g_2x12_ss_2mh: CON,2X12P,F,ATX PWR,S,TH; CLASS: IO; DPN: JT640; Lead Free: Yes; Lifecycle Phase: Preliminary; Manufacturer: FOXCONN; Manufacturer PN: HM3512E-P2; Package Height: 13.1826 MM; Package Type: TH; Part Number: JT640; Rev: Introductory
Q1 Q2 = ft2n7002k_sot23: TRANS,FET,NCHN,60V,SOT23,ESD1K; CLASS: DISCRETE; DPN: FR033; Lead Free: Yes; Lifecycle Phase: A Revision; Manufacturer: NXP SEMICONDUCTOR; Package Height: 1.17 MM; Package Size: SOT23; Package Type: SMD; Part Number: FR033; Polarity: N-Channel; Rated Voltage: 60V; Rev: A00-00
R94 = res: RES,100,1/16W,1%,THKFLM,0402; CLASS: DISCRETE; DPN: 33JXG; Lead Free: Yes; Lifecycle Phase: A Revision; Manufacturer: KOA; Manufacturer PN: RK73H1ETTP1000F; Material: Thick Film; Package Height: 16 MIL; Package Size: 0402; Package Type: SMD; Part Number: 33JXG; Rated Power: 62.5mW; Rev: A00-00; Tolerance: 1%
R95 R97 = res: RES,130,1/16W,1%,THKFLM,0402; CLASS: DISCRETE; DPN: J8387; Lead Free: Yes; Lifecycle Phase: A Revision; Manufacturer: KOA; Manufacturer PN: RK73H1ETTP1300F; Material: Thick Film; Package Height: 16 MIL; Package Size: 0402; Package Type: SMD; Part Number: J8387; ROOM: BRD1; Rated Power: 62.5mW; Rev: A00-00; Tolerance: 1%
R96 = res: RES,240,1/16W,1%,0402,SMD; CLASS: DISCRETE; DPN: P702J; Lead Free: Yes; Lifecycle Phase: A Revision; Manufacturer: KOA; Manufacturer PN: RK73H1ETTP2400F; Package Height: 16 MIL; Package Size: 0402; Package Type: SMD; Part Number: P702J; Rated Power: 62.5mW; Rev: A00-00; Tolerance: 1%
R98 = res: RES,300,1/16W,5%,THKFLM,0402; CLASS: DISCRETE; DPN: G3731; Lead Free: Yes; Lifecycle Phase: A Revision; Manufacturer: SEI ELECTRONICS INC; Manufacturer PN: RMCF 1/16S 300 5%; Material: Thick Film; Package Height: 16 MIL; Package Size: 0402; Package Type: SMD; Part Number: G3731; Rated Power: 62.5mW; Rev: A00-00; Tolerance: 5%
R99 = res: RES,120,1/16W,1%,THKFLM,0402; CLASS: DISCRETE; DPN: YR3NG; Lead Free: Yes; Lifecycle Phase: A Revision; Manufacturer: SEI ELECTRONICS INC; Manufacturer PN: RMCF0402FT120R; Material: Thick Film; Package Height: 16 MIL; Package Size: 0402; Package Type: SMD; Part Number: YR3NG; Rated Power: 62.5mW; Rev: A00-00; Tolerance: 1%
U9 = lm317l: IC,LM317L,SO8,VOLT.REG; CLASS: IC; DPN: 9F006; Lead Free: No; Lifecycle Phase: A Revision; Manufacturer: NATIONAL SEMICONDUCTOR; Manufacturer PN: LM317LM; Package Height: 1.75 MM; Package Size: SO8; Package Type: SMD; Part Number: 9F006; Rev: A00-00
U10 = lm337: IC,LM337,SO223,NEG ADJ,V REG; CLASS: IC; DPN: 083XW; Lead Free: No; Lifecycle Phase: A Revision; Manufacturer: NATIONAL SEMICONDUCTOR; Manufacturer PN: LM337IMP; Package Height: 1.8 MM; Package Size: SO223; Package Type: SMD; Part Number: 083XW; Rev: A00-00

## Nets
GND: C1.1 C2.1 C3.1 C4.1 C5.2 C6.1 C7.1 C8.1 C9.1 C10.2 C11.2 C12.1 C13.1 C14.2 C15.2 C16.2 C19.1 C20.1 C21.2 C22.1 C23.2 C25.1 C26.1 C36.1 C37.1 C38.1 C39.1 C40.2 C41.1 C42.1 C43.1 C44.1 C45.1 C46.2 C47.1 C49.1 C50.1 C51.2 C52.1 C53.2 C54.2 C55.1 C56.1 C57.2 C58.1 C130.2 C131.2 C132.2 C133.2 C134.2 C135.2 C136.2 C137.2 C138.2 C139.2 C140.1 C141.1 C142.2 C143.2 C144.2 C145.2 C146.2 C147.2 C148.2 C149.2 C150.2 C151.2 C152.2 DS1.3(E) DS2.3(E) DS_3P3V.2(C) DS_5VSTBY.2(C) P1.2 P2.2 P3.2 P4.2 P6.4 P7.4 P_ATX.3 P_ATX.5 P_ATX.7 P_ATX.15 P_ATX.17 P_ATX.18 P_ATX.19 P_ATX.24 P_CMTS_N.MH1 P_CMTS_N.MH2 P_CMTS_N.MH3 P_CMTS_N.MH4 P_CMTS_P.MH1 P_CMTS_P.MH2 P_CMTS_P.MH3 P_CMTS_P.MH4 P_EXT_CLK_N.MH1 P_EXT_CLK_N.MH2 P_EXT_CLK_N.MH3 P_EXT_CLK_N.MH4 P_EXT_CLK_P.MH1 P_EXT_CLK_P.MH2 P_EXT_CLK_P.MH3 P_EXT_CLK_P.MH4 P_NOISEINJ_N.MH1 P_NOISEINJ_N.MH2 P_NOISEINJ_N.MH3 P_NOISEINJ_N.MH4 P_NOISEINJ_P.MH1 P_NOISEINJ_P.MH2 P_NOISEINJ_P.MH3 P_NOISEINJ_P.MH4 P_OCP.A1 P_OCP.A2 P_OCP.A3 P_OCP.A4 P_OCP.A5 P_OCP.A6 P_OCP.A10 P_OCP.A13 P_OCP.A16 P_OCP.A19 P_OCP.A22 P_OCP.A25 P_OCP.A28 P_OCP.A29 P_OCP.A32 P_OCP.A35 P_OCP.A38 P_OCP.A41 P_OCP.A43 P_OCP.A46 P_OCP.A49 P_OCP.A52 P_OCP.A55 P_OCP.A58 P_OCP.A61 P_OCP.A64 P_OCP.A67 P_OCP.B13 P_OCP.B16 P_OCP.B19 P_OCP.B22 P_OCP.B25 P_OCP.B28 P_OCP.B29 P_OCP.B32 P_OCP.B35 P_OCP.B38 P_OCP.B41 P_OCP.B43 P_OCP.B46 P_OCP.B49 P_OCP.B52 P_OCP.B55 P_OCP.B58 P_OCP.B61 P_OCP.B64 P_OCP.B67 P_OCP.OCP_A6 P_OCP.OCP_A10 P_OCP.OCP_A13 P_OCP.OCP_B10 P_OCP.OCP_B13 Q1.2(S) Q2.2(S) R6.1 R7.1 R11.1 R14.1 R18.1 R33.1 R47.1 R48.1 R49.1 R72.1 R73.1 R78.1 R79.1 R81.1 R82.1 R83.1 R84.1 R90.1 R91.1 R92.1 R93.1 R94.1 R100.1 R188.2 R193.1 R202.1 R208.1 R209.1 R210.2 R212.1 R213.1 R214.1 R215.1 SW1.2 SW2.3 SW_PWR.6 U1.3(GND) U2.3(GND) U3.1(GND) U4.3(GND) U5.3(GND) U6.3(GND) U7.3(GND) U8.3(GND) U17.2(GND) U18.5(VSSR) U18.9(GND_1) U18.11(GND_2) U18.20(GND_3) U18.21(EPAD) U19.29(EPAD) U20.7(GND) ; also on sheet 8 9 10 11 12 13
GND_OSC1: R45.1 R47.2 X_OSC1.3(GND)
VCC_OSC1: C23.1 R35.1 R36.1 R37.1 X_OSC1.6(VDD)
317_ADJ: R94.2 R96.1 U9.4(ADJ)
337_ADJ: R99.1 R100.2 U10.1(ADJ)
555_DISCHARGE: C10.1 R23.2 R24.1 U3.6(THRESHOLD) U3.7(DISCHARGE)
555_OUT: R27.1 R29.2 U3.3(OUT)
555_OUT_JP: P3.1 R27.2
555_RST_N: C11.1 R26.2 U3.4(RESET_N)
555_TRI: R19.2 R25.2 U3.2(TRIGGER_N)
ATX_PS_ON_N: DS2.4(COL) P_ATX.16 SW_PWR.5
ATX_PWR_OK: P_ATX.8 ; also on sheet 8
AUX_PWR_EN: P_OCP.B12 ; also on sheet 8
BIF0_N: P_OCP.B7 R12.2 R14.2
BIF1_N: P_OCP.B8 R6.2 R13.2
BIF2_N: P_OCP.B9 R5.2 R7.2
BTN_NC: R20.1 R31.1 SW1.1 U1.1(A)
BTN_NO: DS1.4(COL) R19.1 R28.1 SW1.3 U6.2(B)
BUS_SEL: C15.1 P4.1 Q2.1(G) R29.1 R30.1 R31.2 U8.10(SEL)
CLK_BASE_TO_DEVICE_DN: R55.2 R111.1 R113.1 R115.1 R117.1 SW_BUF_SRC.5 U19.7(CLKINb_DN)
CLK_BASE_TO_DEVICE_DP: R56.2 R110.1 R112.1 R114.1 R116.1 SW_BUF_SRC.2 U19.6(CLKIN_DP)
CLK_BASE_TO_DEVICE_R_DN: P_NOISEINJ_N.1 R55.1
CLK_BASE_TO_DEVICE_R_DP: P_NOISEINJ_P.1 R56.1
CLK_EXTERNAL_DN: C25.2 P_EXT_CLK_N.1 R53.1 SW_BUF_SRC.6
CLK_EXTERNAL_DP: C26.2 P_EXT_CLK_P.1 R54.1 SW_BUF_SRC.3
CLK_NCSI: P_OCP.OCP_A14 TP18.TEST
CLK_OSC1_TO_TRIGGER_DN: R38.1 R48.2 R53.2 U8.6(D-) X_OSC1.5(OUT_N)
CLK_OSC1_TO_TRIGGER_DP: R39.1 R49.2 R54.2 U8.7(D+) X_OSC1.4(OUT)
CLK_OSC2_TO_DEVICE_DN: R44.1 SW_BUF_SRC.4 U18.13(DIFF_0b_DN)
CLK_OSC2_TO_DEVICE_DP: R43.1 SW_BUF_SRC.1 U18.12(DIFF_0_DP)
CLK_TRIG_SIGNAL_C_DN: C18.1 R34.1
CLK_TRIG_SIGNAL_C_DP: C17.1 R32.1
CLK_TRIG_SIGNAL_DN: C18.2 U8.2(Y-)
CLK_TRIG_SIGNAL_DP: C17.2 U8.1(Y+)
CLK_TRIG_SIGNAL_R_DN: P_CMTS_N.1 R34.2
CLK_TRIG_SIGNAL_R_DP: P_CMTS_P.1 R32.2
CLKBUF_EN: U18.1(PWRGD/PWRDNb_N) ; also on sheet 8
CLKBUF_EN_N: U20.2(1A) U20.5(2A) U20.9(3A) U20.12(4A) ; also on sheet 8
CLKBUF_OE0_N: SW_OE0.2 U19.22(OEb2_SBI_OUT_N) U20.3(1B)
CLKBUF_OE0_OFF: R86.1 SW_OE0.1
CLKBUF_OE0_ON: R90.2 SW_OE0.3
CLKBUF_OE0_OVERRIDE: R210.1 SW_OE0.5 U20.1(1OE_N)
CLKBUF_OE1_N: SW_OE1.2 U19.14(OEb9_SBI_IN_N) U20.6(2B)
CLKBUF_OE1_OFF: R87.1 SW_OE1.1
CLKBUF_OE1_ON: R91.2 SW_OE1.3
CLKBUF_OE1_OVERRIDE: R213.2 SW_OE1.5 U20.4(2OE_N)
CLKBUF_OE2_N: SW_OE2.2 U19.21(OEb5_SBI_CLK_N) U20.8(3B)
CLKBUF_OE2_OFF: R88.1 SW_OE2.1
CLKBUF_OE2_ON: R92.2 SW_OE2.3
CLKBUF_OE2_OVERRIDE: R214.2 SW_OE2.5 U20.10(3OE_N)
CLKBUF_OE3_N: SW_OE3.2 U19.11(OEb13_SHFT_LDb_N) U20.11(4B)
CLKBUF_OE3_OFF: R89.1 SW_OE3.1
CLKBUF_OE3_ON: R93.2 SW_OE3.3
CLKBUF_OE3_OVERRIDE: R215.2 SW_OE3.5 U20.13(4OE_N)
MAIN_PWR_EN: P_OCP.OCP_B2 U19.9(PWRGD_PWRDNb) ; also on sheet 8
NC1_A68: P_OCP.A68
NC1_A69: P_OCP.A69
NC1_A70: P_OCP.A70
NC1_B69: P_OCP.B69
NCSI_ARBIN: P_OCP.OCP_A4 TP12.TEST
NCSI_ARBOUT: P_OCP.OCP_A5 TP15.TEST
NCSI_CRS_DV: P_OCP.OCP_B14 TP17.TEST
NCSI_RXD0: P_OCP.OCP_B9 TP9.TEST
NCSI_RXD1: P_OCP.OCP_B8 TP7.TEST
NCSI_TXD0: P_OCP.OCP_A9 TP10.TEST
NCSI_TXD1: P_OCP.OCP_A8 TP8.TEST
NCSI_TXEN: P_OCP.OCP_A7 TP16.TEST
NIC_PWR_GOOD: P_OCP.OCP_B1 ; also on sheet 8
PCIE_RST_BTN_N: Q1.1(G) R2.2 R8.2 R15.1 R16.2 ; also on sheet 8
PE_CPU_OCP_0_DN: P_OCP.B17 ; also on sheet 9
PE_CPU_OCP_0_DP: P_OCP.B18 ; also on sheet 9
PE_CPU_OCP_1_DN: P_OCP.B20 ; also on sheet 9
PE_CPU_OCP_1_DP: P_OCP.B21 ; also on sheet 9
PE_CPU_OCP_2_DN: P_OCP.B23 ; also on sheet 9
PE_CPU_OCP_2_DP: P_OCP.B24 ; also on sheet 9
PE_CPU_OCP_3_DN: P_OCP.B26 ; also on sheet 9
PE_CPU_OCP_3_DP: P_OCP.B27 ; also on sheet 9
PE_CPU_OCP_4_DN: P_OCP.B30 ; also on sheet 10
PE_CPU_OCP_4_DP: P_OCP.B31 ; also on sheet 10
PE_CPU_OCP_5_DN: P_OCP.B33 ; also on sheet 10
PE_CPU_OCP_5_DP: P_OCP.B34 ; also on sheet 10
PE_CPU_OCP_6_DN: P_OCP.B36 ; also on sheet 10
PE_CPU_OCP_6_DP: P_OCP.B37 ; also on sheet 10
PE_CPU_OCP_7_DN: P_OCP.B39 ; also on sheet 10
PE_CPU_OCP_7_DP: P_OCP.B40 ; also on sheet 10
PE_CPU_OCP_8_DN: P_OCP.B44 ; also on sheet 11
PE_CPU_OCP_8_DP: P_OCP.B45 ; also on sheet 11
PE_CPU_OCP_9_DN: P_OCP.B47 ; also on sheet 11
PE_CPU_OCP_9_DP: P_OCP.B48 ; also on sheet 11
PE_CPU_OCP_10_DN: P_OCP.B50 ; also on sheet 11
PE_CPU_OCP_10_DP: P_OCP.B51 ; also on sheet 11
PE_CPU_OCP_11_DN: P_OCP.B53 ; also on sheet 11
PE_CPU_OCP_11_DP: P_OCP.B54 ; also on sheet 11
PE_CPU_OCP_12_DN: P_OCP.B56 ; also on sheet 12
PE_CPU_OCP_12_DP: P_OCP.B57 ; also on sheet 12
PE_CPU_OCP_13_DN: P_OCP.B59 ; also on sheet 12
PE_CPU_OCP_13_DP: P_OCP.B60 ; also on sheet 12
PE_CPU_OCP_14_DN: P_OCP.B62 ; also on sheet 12
PE_CPU_OCP_14_DP: P_OCP.B63 ; also on sheet 12
PE_CPU_OCP_15_DN: P_OCP.B65 ; also on sheet 12
PE_CPU_OCP_15_DP: P_OCP.B66 ; also on sheet 12
PE_OCP_CPU_0_DN: P_OCP.A17 ; also on sheet 9
PE_OCP_CPU_0_DP: P_OCP.A18 ; also on sheet 9
PE_OCP_CPU_1_DN: P_OCP.A20 ; also on sheet 9
PE_OCP_CPU_1_DP: P_OCP.A21 ; also on sheet 9
PE_OCP_CPU_2_DN: P_OCP.A23 ; also on sheet 9
PE_OCP_CPU_2_DP: P_OCP.A24 ; also on sheet 9
PE_OCP_CPU_3_DN: P_OCP.A26 ; also on sheet 9
PE_OCP_CPU_3_DP: P_OCP.A27 ; also on sheet 9
PE_OCP_CPU_4_DN: P_OCP.A30 ; also on sheet 10
PE_OCP_CPU_4_DP: P_OCP.A31 ; also on sheet 10
PE_OCP_CPU_5_DN: P_OCP.A33 ; also on sheet 10
PE_OCP_CPU_5_DP: P_OCP.A34 ; also on sheet 10
PE_OCP_CPU_6_DN: P_OCP.A36 ; also on sheet 10
PE_OCP_CPU_6_DP: P_OCP.A37 ; also on sheet 10
PE_OCP_CPU_7_DN: P_OCP.A39 ; also on sheet 10
PE_OCP_CPU_7_DP: P_OCP.A40 ; also on sheet 10
PE_OCP_CPU_8_DN: P_OCP.A44 ; also on sheet 11
PE_OCP_CPU_8_DP: P_OCP.A45 ; also on sheet 11
PE_OCP_CPU_9_DN: P_OCP.A47 ; also on sheet 11
PE_OCP_CPU_9_DP: P_OCP.A48 ; also on sheet 11
PE_OCP_CPU_10_DN: P_OCP.A50 ; also on sheet 11
PE_OCP_CPU_10_DP: P_OCP.A51 ; also on sheet 11
PE_OCP_CPU_11_DN: P_OCP.A53 ; also on sheet 11
PE_OCP_CPU_11_DP: P_OCP.A54 ; also on sheet 11
PE_OCP_CPU_12_DN: P_OCP.A56 ; also on sheet 12
PE_OCP_CPU_12_DP: P_OCP.A57 ; also on sheet 12
PE_OCP_CPU_13_DN: P_OCP.A59 ; also on sheet 12
PE_OCP_CPU_13_DP: P_OCP.A60 ; also on sheet 12
PE_OCP_CPU_14_DN: P_OCP.A62 ; also on sheet 12
PE_OCP_CPU_14_DP: P_OCP.A63 ; also on sheet 12
PE_OCP_CPU_15_DN: P_OCP.A65 ; also on sheet 12
PE_OCP_CPU_15_DP: P_OCP.A66 ; also on sheet 12
PERST0_N: P_OCP.B10 R15.2
PERST1_N: P_OCP.A11 R16.1
PERST2_N: P_OCP.OCP_A1 R2.1
PERST3_N: P_OCP.OCP_A2 R8.1
PRSNTB0_N: P_OCP.B42 R1.1 TP1.TEST
PRSNTB1_N: P_OCP.A42 R3.1 TP2.TEST
PRSNTB2_N: P_OCP.A12 R4.1 TP13.TEST
PRSNTB3_N: P_OCP.B70 R10.1 TP6.TEST
PWRBRK_N: P_OCP.B68 R17.2 R18.2
RC19004_VDDCLK1: C142.1 C143.1 L7.2 U19.10(VDDCLK_1)
RC19004_VDDCLK2: C144.1 C145.1 L8.2 U19.15(VDDCLK_2)
RC19004_VDDCLK3: C148.1 C149.1 L9.2 U19.18(VDDCLK_3)
RC19004_VDDCLK4: C150.1 C151.1 L10.2 U19.25(VDDCLK_4)
REFCLK0_DN: P_OCP.B14 R78.2 R111.2 R196.2
REFCLK0_DP: P_OCP.B15 R72.2 R110.2 R195.2
REFCLK0_R_DN: R196.1 U19.13(CLKb13_DN)
REFCLK0_R_DP: R195.1 U19.12(CLK13_DP)
REFCLK1_DN: P_OCP.A14 R83.2 R113.2 R198.2
REFCLK1_DP: P_OCP.A15 R81.2 R112.2 R197.2
REFCLK1_R_DN: R198.1 U19.17(CLKb9_DN)
REFCLK1_R_DP: R197.1 U19.16(CLK9_DP)
REFCLK2_DN: P_OCP.OCP_B11 R79.2 R115.2 R200.2
REFCLK2_DP: P_OCP.OCP_B12 R73.2 R114.2 R199.2
REFCLK2_R_DN: R200.1 U19.20(CLKb5_DN)
REFCLK2_R_DP: R199.1 U19.19(CLK5_DP)
REFCLK3_DN: P_OCP.OCP_A11 R70.2 R84.2 R117.2
REFCLK3_DP: P_OCP.OCP_A12 R82.2 R116.2 R201.2
REFCLK3_R_DN: R70.1 U19.24(CLKb2_DN)
REFCLK3_R_DP: R201.1 U19.23(CLK2_DP)
SCAN_CLK: P_OCP.OCP_B6 TP5.TEST
SCAN_DATA_IN: P_OCP.OCP_B4 TP11.TEST
SCAN_DATA_OUT: P_OCP.OCP_B5 TP14.TEST
SCAN_LD_N: P_OCP.OCP_B3 TP3.TEST
SI52202_1P8V: L3.1 L4.1 L5.1 L6.1 U17.5(OUT)
SI52202_SADR1: R206.1 R207.1 R208.2 R209.2 U19.1(SADR_tri1) U19.2(SADR_tri0)
SI52202_SCLK: P6.2 R191.1 U18.7(SCLK)
SI52202_SCLK (page PAGE06 - REFCLK BUFFER): P7.2 R205.1 U19.4(SCLK)
SI52202_SDA: P6.3 R192.1 U18.6(SDA)
SI52202_SDA (page PAGE06 - REFCLK BUFFER): P7.3 R204.1 U19.3(SDATA)
SI52202_SLEWRATE_SEL: P_SLEWRATE_SEL.1 R211.1 U19.27(SLEWRATE_SEL)
SI52202_VDD: C134.1 C135.1 L4.2 U18.10(VDD)
SI52202_VDDA: C138.1 C139.1 L6.2 U18.19(VDDA)
SI52202_VDDIO: C136.1 C137.1 L5.2 U18.15(VDD_IO)
SI52202_VDDX: C132.1 C133.1 L3.2 U18.4(VDDX)
SI52202_XIN: C140.2 U18.2(XIN/CLKIN) X1.1
SI52202_XOUT: C141.2 U18.3(XOUT) X1.3
SLOT_ID: P_OCP.OCP_B7 R9.1 R11.2
SMB_CLK: P_OCP.A7 TP19.TEST
SMB_RST_N: P_OCP.A9 TP21.TEST
SMB_SDA: P_OCP.A8 TP20.TEST
V_1P65: C37.2 C38.2 C39.2 C40.1 C41.2 R35.2 R96.2 U9.2(VOUT1) U9.3(VOUT2) U9.6(VOUT3) U9.7(VOUT4)
V_1P65_NEG: C43.2 C44.2 C45.2 C46.1 C47.2 R45.2 R99.2 U10.3(VOUT)
V_3P3: C3.2 C4.2 C5.1 C6.2 C7.2 C8.2 C9.2 C12.2 C13.2 C16.1 C19.2 C20.2 C21.1 C22.2 C49.2 C50.2 C51.1 C52.2 C130.1 C131.1 C146.1 C147.1 C152.1 L7.1 L8.1 L9.1 L10.1 P6.1 P7.1 P_ATX.1 P_ATX.2 P_ATX.12 P_ATX.13 P_OCP.B11 R1.2 R3.2 R4.2 R5.1 R9.2 R10.2 R12.1 R13.1 R17.1 R20.2 R23.1 R24.2 R26.1 R28.2 R30.2 R36.2 R38.2 R39.2 R43.2 R44.2 R86.2 R87.2 R88.2 R89.2 R95.1 R97.1 R186.2 R187.2 R191.2 R192.2 R203.2 R204.2 R205.2 R206.2 R207.2 R211.2 SW2.1 SW_OE0.4 SW_OE0.6 SW_OE1.4 SW_OE1.6 SW_OE2.4 SW_OE2.6 SW_OE3.4 SW_OE3.6 U1.5(VCC) U2.5(VCC) U3.8(V+) U4.5(VCC) U5.5(VCC) U6.5(VCC) U7.5(VCC) U8.9(VDD) U17.1(IN) U19.5(VDDDIG) U20.14(VCC) ; also on sheet 8
V_5V: C36.2 P_ATX.4 P_ATX.6 P_ATX.21 P_ATX.22 P_ATX.23 U9.1(VIN)
V_5VSTBY: P_ATX.9 R98.1
V_12V: C1.2 C2.2 C48.1 C53.1 C54.1 C55.2 P_ATX.10 P_ATX.11 P_OCP.B1 P_OCP.B2 P_OCP.B3 P_OCP.B4 P_OCP.B5 P_OCP.B6 R101.1
V_12V_NEG: C42.2 C56.2 C57.1 C58.2 P_ATX.14 U10.2(VIN) U10.4(VIN)
WAKE_N: P_OCP.OCP_A3 TP4.TEST
N16775589: R21.2 U1.4(Y) U2.1(A) U4.1(A) U5.1(A) U5.2(B) U6.1(A)
N16775601: P2.1 R21.1
N16775717: U1.2(B) U6.4(Y)
N16776117: U2.2(B) U4.4(Y) U7.1(A)
N16776223: U4.2(B) U7.4(Y)
N16776317: C14.1 U5.4(Y) U7.2(B)
N16776527: R22.2 R25.1 U2.4(Y)
N16776623: P1.1 R22.1
N16777522: R33.2 U8.8(OE_N)
N16798679: R37.2 X_OSC1.1(E/D)
N16831523: DS_3P3V.1(A) R97.2
N16831963: DS_5VSTBY.1(A) R98.2
N16832324: DS_RST.2(C) Q1.3(D)
N16832328: DS_RST.1(A) R95.2
N16833101: DS_TRIG.1(A) R101.2
N16833103: C48.2 DS_TRIG.2(C) Q2.3(D)
N17027072: R202.2 U19.8(SBI_ENQ)
N17042432: R187.1 R193.2 SW2.2(C_1) U18.8(SS_EN)
N17054983: R186.1 U17.3(EN)
N17056716: R188.1 U18.14(OE_0b)
N17056744: R203.1 U18.16(OE_1b)
N17069423: P_SLEWRATE_SEL.2 R212.2
N17072145: DS2.1(A) R217.1
N17072148: P9.2 R217.2
N17072154: DS2.2(C) P9.1
N17072580: P8.2 R216.2
N17072594: DS1.2(C) P8.1
N17073631: DS1.1(A) R216.1

Not connected (* = marked no-connect by the designer): LBL1 1(NC); P_ATX 20*; SW2 4 5(C_2) 6; SW_PWR 1* 2* 3* 4*; U3 5(CNTRL_VLT)*; U8 4(M-)* 5(M+)*; U9 5(NC5)* 8(NC8)*; U17 4(NC)*; U18 17(DIFF_1_DP)* 18(DIFF_1b_DN)*; U19 26(NC)* 28(LOSb); X_OSC1 2(NC)*

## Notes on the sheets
sheet 1
- Table of Contents:
  Page 1: Title, Block Diagram
  Page 2: Stackup
  Page 3: OCP Straddle Mount Conn
  Page 4: Comp Mode Toggle Signal
  Page 5: Clocks
  Page 6: Clock Buffer
  Page 7: Power
  Page 8: Power Sequence
  Page 9: PCIe Lanes 0-3
  Page 10: PCIe Lanes 4-7
  Page 11: PCIe Lanes 8-11
  Page 12: PCIe Lanes 12-15
  Page 13: Coupons
  Page 14: CBB Calibration Board
- PWA: JGWMJ
  PWB: 7YKPM
  Sch: X07NT
sheet 2
- Stackup
sheet 3
- OCP3 Small Form Factor Connector
  (Vertical)
- PRSNTA_N
- ROOM = OCPCONN
sheet 4
- RSVD TEST
- CMTS
- CMTS AUTOMATION CONNECTOR
- CMTS OUT
- ROOM = CMTS
sheet 5
- OSC1
- Updated to GDYTG
- OSC2
- NOISE INJECTION
- EXT CLK IN
sheet 6
- CLK BUFFER
- Imp: 85ohm, Rs=33ohm, Rt=43.2ohm
sheet 7
- POWER
- LEDs
- Power Switch
- RESET AUTOMATION CONNECTOR
